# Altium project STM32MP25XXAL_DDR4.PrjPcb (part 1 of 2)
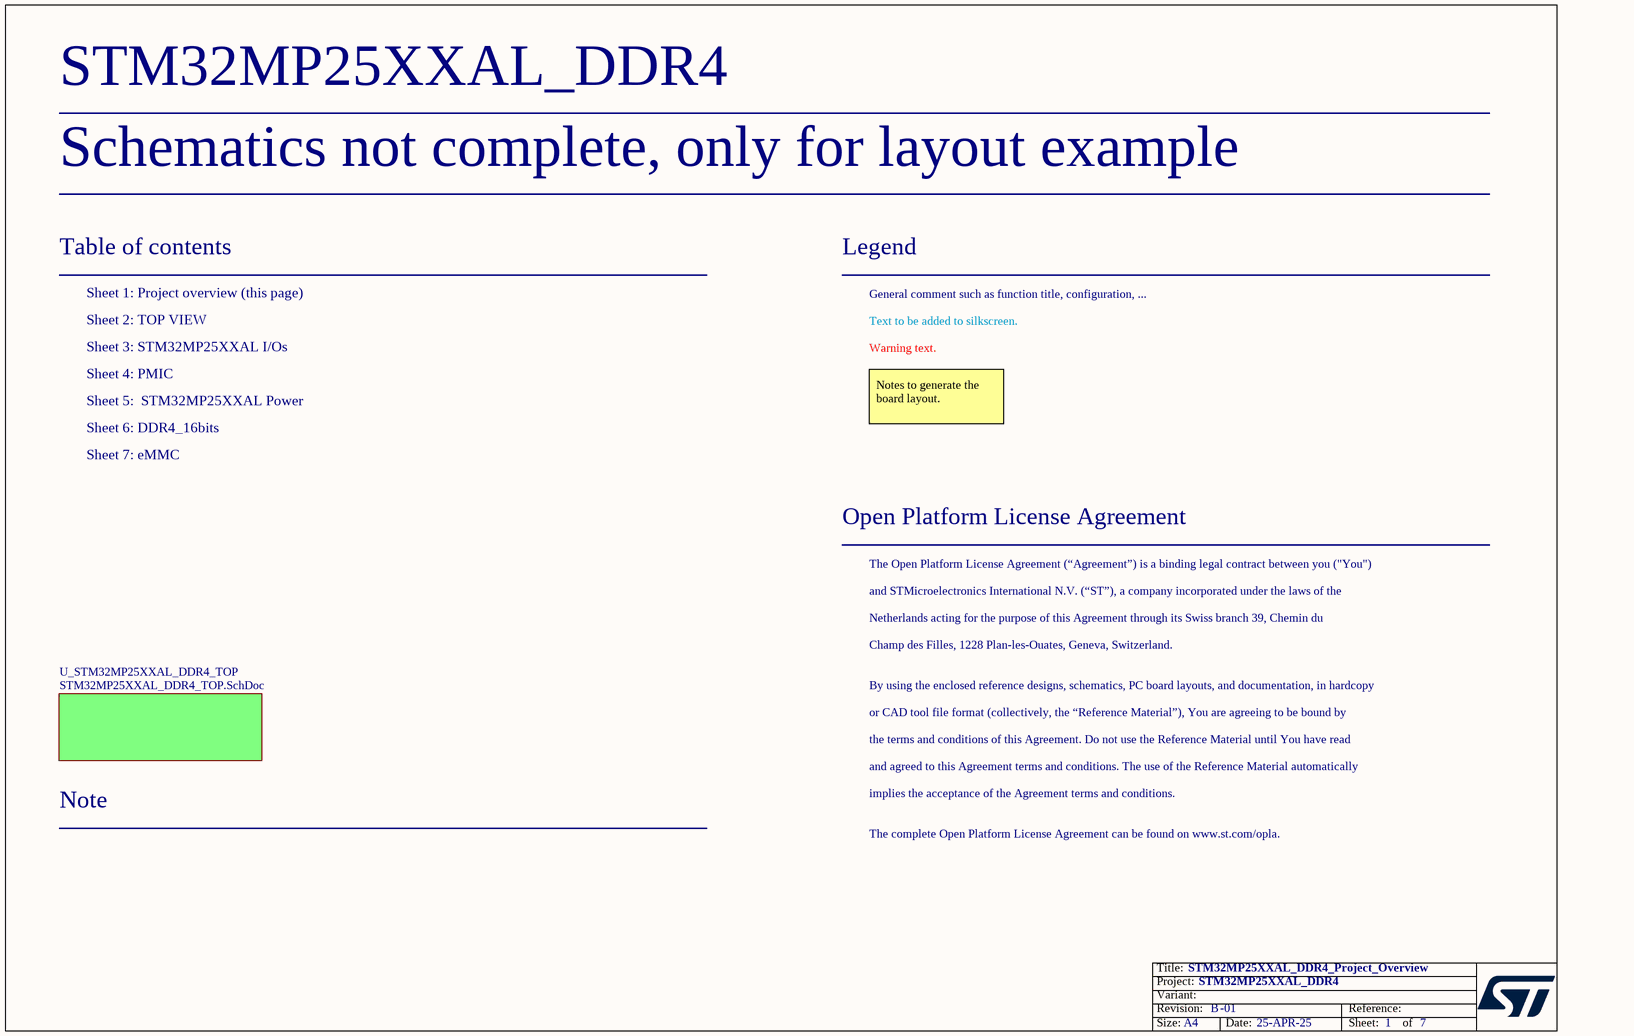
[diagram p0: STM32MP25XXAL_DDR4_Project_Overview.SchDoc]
Board_Assembly_Revision: 01; Board_Document_Date: 25-APR-25; Board_Name: STM32MP25XXAL_DDR4; Board_PCB_Revision: B
7 sheets, 220 parts. Net scope: flat (ports and power ports of the same name join across sheets).
Board file: STM32MP25XXAL_DDR4.PcbDoc
Sheets:
  STM32MP25XXAL_DDR4_Project_Overview.SchDoc
    U_STM32MP25XXAL_DDR4_TOP = STM32MP25XXAL_DDR4_TOP.SchDoc
      U_STM32MP25XXAL I_Os = STM32MP25XXAL I_Os.SchDoc
      U_PMIC = PMIC.SchDoc
      U_STM32MP25XXAL Power = STM32MP25XXAL Power.SchDoc
      U_eMMC = eMMC.SchDoc
      U_DDR4_16bits = DDR4_16bits.SchDoc

## Sheet STM32MP25XXAL_DDR4_Project_Overview.SchDoc: STM32MP25XXAL_DDR4_Project_Overview
size A4; Date: Not used; ApprovedBy: Not used; CheckedBy: Not used; Author: Not used; CompanyName: STMicroelectronics; DrawnBy: Not used; Engineer: Not used; Organization: Not used; Address1: Not used; Address2: Not used; Address3: Not used; Address4: Not used; DocumentNumber: 1; Revision: Not used; SheetNumber: 1; SheetTotal: 7

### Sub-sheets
U_STM32MP25XXAL_DDR4_TOP = STM32MP25XXAL_DDR4_TOP.SchDoc: no entries

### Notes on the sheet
- Schematics not complete, only for layout example
- Table of contents
- Sheet 1: Project overview (this page)
- Legend
- General comment such as function title, configuration, ...
- Sheet 2: TOP VIEW
- Sheet 3: STM32MP25XXAL I/Os
- Sheet 4: PMIC
- Text to be added to silkscreen.
- Warning text.
- Sheet 5:  STM32MP25XXAL Power
- Sheet 6: DDR4_16bits
- Notes to generate the board layout.
- Sheet 7: eMMC
- Open Platform License Agreement
- The Open Platform License Agreement (“Agreement”) is a binding legal contract between you ("You")
- and STMicroelectronics International N.V. (“ST”), a company incorporated under the laws of the
- Netherlands acting for the purpose of this Agreement through its Swiss branch 39, Chemin du
- Champ des Filles, 1228 Plan-les-Ouates, Geneva, Switzerland.
- By using the enclosed reference designs, schematics, PC board layouts, and documentation, in hardcopy
- or CAD tool file format (collectively, the “Reference Material”), You are agreeing to be bound by
- the terms and conditions of this Agreement. Do not use the Reference Material until You have read
- and agreed to this Agreement terms and conditions. The use of the Reference Material automatically
- Note
- implies the acceptance of the Agreement terms and conditions.
- The complete Open Platform License Agreement can be found on www.st.com/opla.

## Sheet STM32MP25XXAL_DDR4_TOP.SchDoc: TOP
size A4; Date: Not used; ApprovedBy: Not used; CheckedBy: Not used; Author: Not used; CompanyName: STMicroelectronics; DrawnBy: Not used; Engineer: Not used; Organization: Not used; Address1: Not used; Address2: Not used; Address3: Not used; Address4: Not used; DocumentNumber: 2; Revision: Not used; SheetNumber: 2; SheetTotal: 7
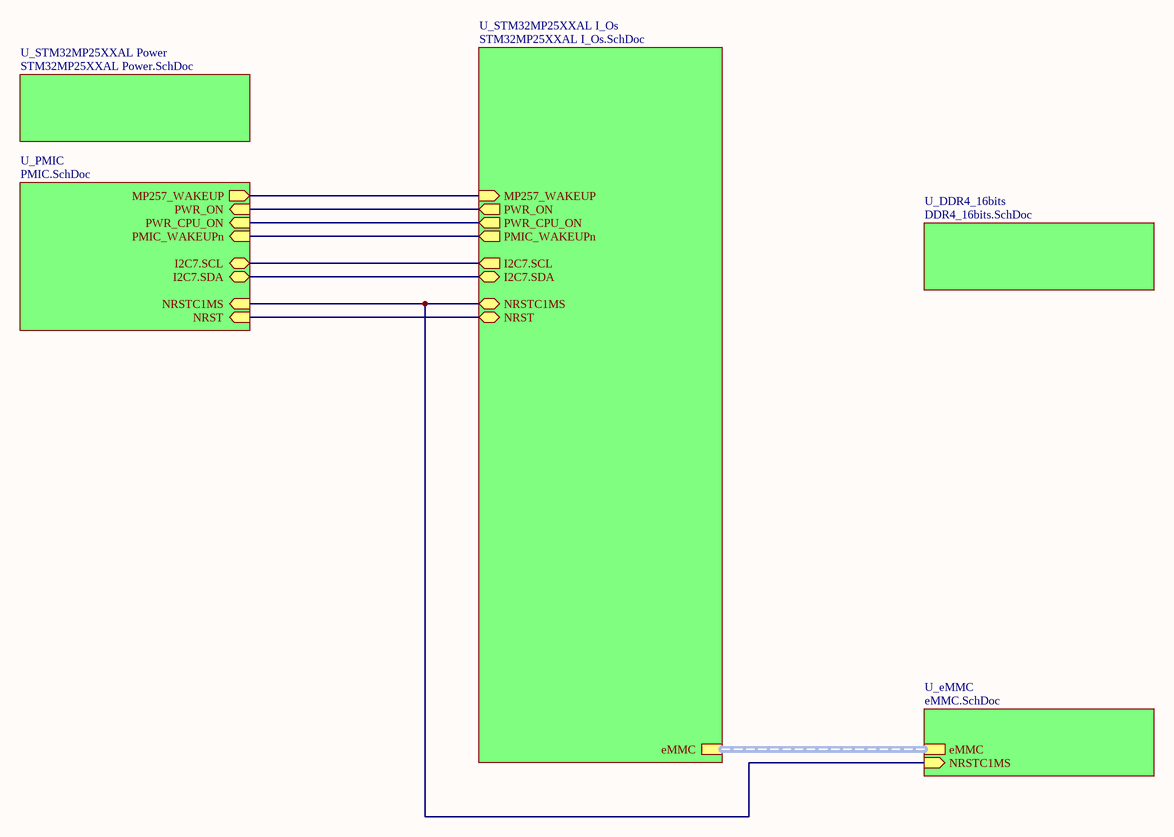
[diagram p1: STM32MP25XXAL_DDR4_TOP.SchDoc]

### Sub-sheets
U_DDR4_16bits = DDR4_16bits.SchDoc: no entries
U_eMMC = eMMC.SchDoc: eMMC (harness eMMC), NRSTC1MS (in)
U_PMIC = PMIC.SchDoc: PMIC_WAKEUPn (in), NRST (in), I2C7.SCL (bidir), PWR_ON (in), PWR_CPU_ON (in), NRSTC1MS (in), I2C7.SDA (bidir), MP257_WAKEUP (out)
U_STM32MP25XXAL I_Os = STM32MP25XXAL I_Os.SchDoc: NRST (bidir), PWR_ON (out), NRSTC1MS (bidir), I2C7.SDA (bidir), I2C7.SCL (out), PWR_CPU_ON (out), MP257_WAKEUP (in), PMIC_WAKEUPn (out), eMMC (harness eMMC)
U_STM32MP25XXAL Power = STM32MP25XXAL Power.SchDoc: no entries

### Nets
(unnamed): sheet U_STM32MP25XXAL I_Os/NRST, sheet U_PMIC/NRST
(unnamed): sheet U_STM32MP25XXAL I_Os/PWR_ON, sheet U_PMIC/PWR_ON  [a separate net that carries the same name]
(unnamed): sheet U_STM32MP25XXAL I_Os/NRSTC1MS, sheet U_PMIC/NRSTC1MS, sheet U_eMMC/NRSTC1MS  [a separate net that carries the same name]
(unnamed): sheet U_STM32MP25XXAL I_Os/I2C7.SDA, sheet U_PMIC/I2C7.SDA  [a separate net that carries the same name]
(unnamed): sheet U_STM32MP25XXAL I_Os/I2C7.SCL, sheet U_PMIC/I2C7.SCL  [a separate net that carries the same name]
(unnamed): sheet U_STM32MP25XXAL I_Os/PWR_CPU_ON, sheet U_PMIC/PWR_CPU_ON  [a separate net that carries the same name]
(unnamed): sheet U_STM32MP25XXAL I_Os/MP257_WAKEUP, sheet U_PMIC/MP257_WAKEUP  [a separate net that carries the same name]
(unnamed): sheet U_STM32MP25XXAL I_Os/PMIC_WAKEUPn, sheet U_PMIC/PMIC_WAKEUPn  [a separate net that carries the same name]

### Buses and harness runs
harness sheet U_eMMC/eMMC = sheet U_STM32MP25XXAL I_Os/eMMC

## Sheet STM32MP25XXAL I_Os.SchDoc: STM32MP25XXAL  I/Os
size A3; Date: Not used; ApprovedBy: Not used; CheckedBy: Not used; Author: Not used; CompanyName: STMicroelectronics; DrawnBy: Not used; Engineer: Not used; Organization: Not used; Address1: Not used; Address2: Not used; Address3: Not used; Address4: Not used; DocumentNumber: 3; Revision: Not used; SheetNumber: 3; SheetTotal: 7
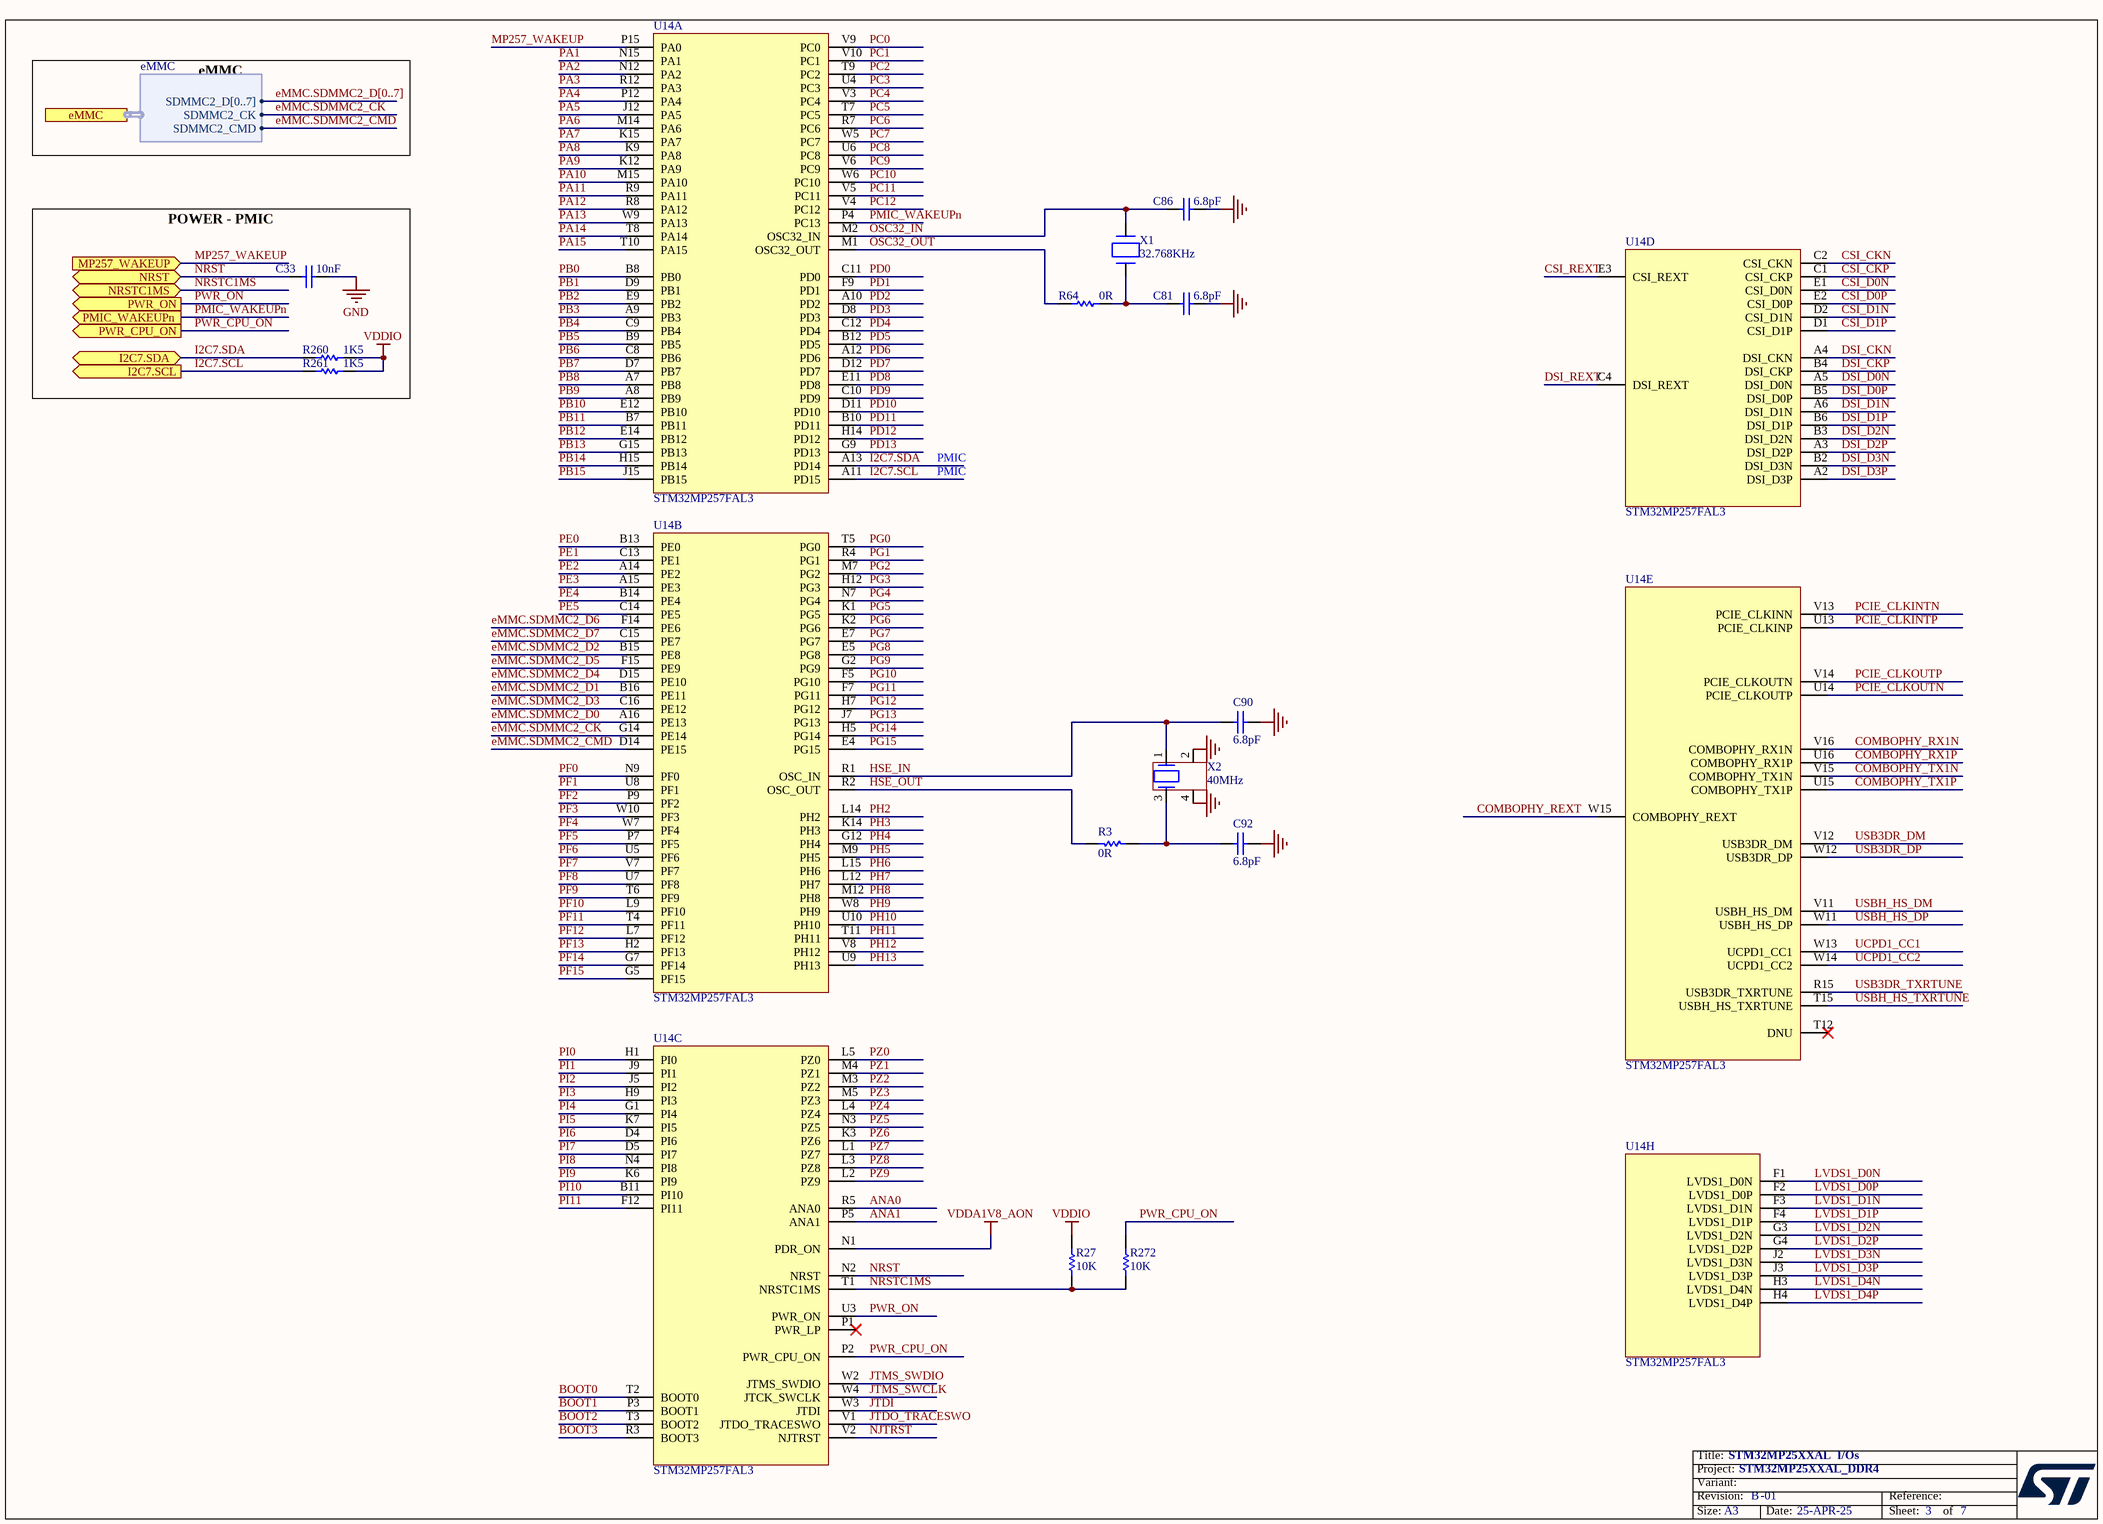
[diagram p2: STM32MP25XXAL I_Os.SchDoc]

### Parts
C33  value 10nF  [C0402]  (hidden comment: Capacitor)
C81  value 6.8pF  [C0402]  (hidden comment: Capacitor)
C86  value 6.8pF  [C0402]  (hidden comment: Capacitor)
C90  value 6.8pF  [C0402]  (hidden comment: Capacitor)
C92  value 6.8pF  [C0402]  (hidden comment: Capacitor)
R3  value 0R  [R0402]
R27  value 10K  [R0402]  (hidden comment: Resistor)
R64  value 0R  [R0402]
R260  value 1K5  [R0402]  (hidden comment: Resistor)
R261  value 1K5  [R0402]  (hidden comment: Resistor)
R272  value 10K  [R0402]  (hidden comment: Resistor)
U14  STM32MP257FAL3  [ICC_VFBGA361_10X10_P050]  (parts A,B,C,D,E,H of 8)
X1  value 32.768KHz  [CRY_NX2012SA_2P]  (hidden comment: XTAL_2_PINS)
X2  value 40MHz  [CRY_NX1612SA_4P]  (hidden comment: XTAL_4_PINS)

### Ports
eMMC (harness eMMC), I2C7.SCL (out), I2C7.SDA (bidir), MP257_WAKEUP (in), NRST (bidir), NRSTC1MS (bidir), PMIC_WAKEUPn (out), PWR_CPU_ON (out), PWR_ON (out)

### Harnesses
eMMC: SDMMC2_CK, SDMMC2_CMD, SDMMC2_D[0..7]

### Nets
GND: C33.1 C81.2 C86.2 C90.1 C92.2 X2.2 X2.4
VDDA1V8_AON: U14.N1(PDR_ON)
VDDIO: R27.2 R260.2 R261.2
ANA0: U14.R5(ANA0)
ANA1: U14.P5(ANA1)
BOOT0: U14.T2(BOOT0)
BOOT1: U14.P3(BOOT1)
BOOT2: U14.T3(BOOT2)
BOOT3: U14.R3(BOOT3)
COMBOPHY_REXT: U14.W15(COMBOPHY_REXT)
COMBOPHY_RX1N: U14.V16(COMBOPHY_RX1N)
COMBOPHY_RX1P: U14.U16(COMBOPHY_RX1P)
COMBOPHY_TX1N: U14.V15(COMBOPHY_TX1N)
COMBOPHY_TX1P: U14.U15(COMBOPHY_TX1P)
CSI_CKN: U14.C2(CSI_CKN)
CSI_CKP: U14.C1(CSI_CKP)
CSI_D0N: U14.E1(CSI_D0N)
CSI_D0P: U14.E2(CSI_D0P)
CSI_D1N: U14.D2(CSI_D1N)
CSI_D1P: U14.D1(CSI_D1P)
CSI_REXT: U14.E3(CSI_REXT)
DSI_CKN: U14.A4(DSI_CKN)
DSI_CKP: U14.B4(DSI_CKP)
DSI_D0N: U14.A5(DSI_D0N)
DSI_D0P: U14.B5(DSI_D0P)
DSI_D1N: U14.A6(DSI_D1N)
DSI_D1P: U14.B6(DSI_D1P)
DSI_D2N: U14.B3(DSI_D2N)
DSI_D2P: U14.A3(DSI_D2P)
DSI_D3N: U14.B2(DSI_D3N)
DSI_D3P: U14.A2(DSI_D3P)
DSI_REXT: U14.C4(DSI_REXT)
eMMC.SDMMC2_CK: U14.G14(PE14) ; port eMMC.SDMMC2_CK
eMMC.SDMMC2_CMD: U14.D14(PE15) ; port eMMC.SDMMC2_CMD
eMMC.SDMMC2_D0: U14.A16(PE13)
eMMC.SDMMC2_D1: U14.B16(PE11)
eMMC.SDMMC2_D2: U14.B15(PE8)
eMMC.SDMMC2_D3: U14.C16(PE12)
eMMC.SDMMC2_D4: U14.D15(PE10)
eMMC.SDMMC2_D5: U14.F15(PE9)
eMMC.SDMMC2_D6: U14.F14(PE6)
eMMC.SDMMC2_D7: U14.C15(PE7)
HSE_IN: C90.2 U14.R1(OSC_IN) X2.1
HSE_OUT: R3.2 U14.R2(OSC_OUT)
I2C7.SCL: R261.1 U14.A11(PD15) ; port I2C7.SCL
I2C7.SDA: R260.1 U14.A13(PD14) ; port I2C7.SDA
JTDI: U14.W3(JTDI)
JTDO_TRACESWO: U14.V1(JTDO_TRACESWO)
JTMS_SWCLK: U14.W4(JTCK_SWCLK)
JTMS_SWDIO: U14.W2(JTMS_SWDIO)
LVDS1_D0N: U14.F1(LVDS1_D0N)
LVDS1_D0P: U14.F2(LVDS1_D0P)
LVDS1_D1N: U14.F3(LVDS1_D1N)
LVDS1_D1P: U14.F4(LVDS1_D1P)
LVDS1_D2N: U14.G3(LVDS1_D2N)
LVDS1_D2P: U14.G4(LVDS1_D2P)
LVDS1_D3N: U14.J2(LVDS1_D3N)
LVDS1_D3P: U14.J3(LVDS1_D3P)
LVDS1_D4N: U14.H3(LVDS1_D4N)
LVDS1_D4P: U14.H4(LVDS1_D4P)
MP257_WAKEUP: U14.P15(PA0) ; port MP257_WAKEUP
NJTRST: U14.V2(NJTRST)
NRST: C33.2 U14.N2(NRST) ; port NRST
NRSTC1MS: R27.1 R272.1 U14.T1(NRSTC1MS) ; port NRSTC1MS
OSC32_IN: C86.1 U14.M2(OSC32_IN) X1.2(X2)
OSC32_OUT: R64.1 U14.M1(OSC32_OUT)
PA1: U14.N15(PA1)
PA2: U14.N12(PA2)
PA3: U14.R12(PA3)
PA4: U14.P12(PA4)
PA5: U14.J12(PA5)
PA6: U14.M14(PA6)
PA7: U14.K15(PA7)
PA8: U14.K9(PA8)
PA9: U14.K12(PA9)
PA10: U14.M15(PA10)
PA11: U14.R9(PA11)
PA12: U14.R8(PA12)
PA13: U14.W9(PA13)
PA14: U14.T8(PA14)
PA15: U14.T10(PA15)
PB0: U14.B8(PB0)
PB1: U14.D9(PB1)
PB2: U14.E9(PB2)
PB3: U14.A9(PB3)
PB4: U14.C9(PB4)
PB5: U14.B9(PB5)
PB6: U14.C8(PB6)
PB7: U14.D7(PB7)
PB8: U14.A7(PB8)
PB9: U14.A8(PB9)
PB10: U14.E12(PB10)
PB11: U14.B7(PB11)
PB12: U14.E14(PB12)
PB13: U14.G15(PB13)
PB14: U14.H15(PB14)
PB15: U14.J15(PB15)
PC0: U14.V9(PC0)
PC1: U14.V10(PC1)
PC2: U14.T9(PC2)
PC3: U14.U4(PC3)
PC4: U14.V3(PC4)
PC5: U14.T7(PC5)
PC6: U14.R7(PC6)
PC7: U14.W5(PC7)
PC8: U14.U6(PC8)
PC9: U14.V6(PC9)
PC10: U14.W6(PC10)
PC11: U14.V5(PC11)
PC12: U14.V4(PC12)
PCIE_CLKINTN: U14.V13(PCIE_CLKINN)
PCIE_CLKINTP: U14.U13(PCIE_CLKINP)
PCIE_CLKOUTN: U14.U14(PCIE_CLKOUTP)
PCIE_CLKOUTP: U14.V14(PCIE_CLKOUTN)
PD0: U14.C11(PD0)
PD1: U14.F9(PD1)
PD2: U14.A10(PD2)
PD3: U14.D8(PD3)
PD4: U14.C12(PD4)
PD5: U14.B12(PD5)
PD6: U14.A12(PD6)
PD7: U14.D12(PD7)
PD8: U14.E11(PD8)
PD9: U14.C10(PD9)
PD10: U14.D11(PD10)
PD11: U14.B10(PD11)
PD12: U14.H14(PD12)
PD13: U14.G9(PD13)
PE0: U14.B13(PE0)
PE1: U14.C13(PE1)
PE2: U14.A14(PE2)
PE3: U14.A15(PE3)
PE4: U14.B14(PE4)
PE5: U14.C14(PE5)
PF0: U14.N9(PF0)
PF1: U14.U8(PF1)
PF2: U14.P9(PF2)
PF3: U14.W10(PF3)
PF4: U14.W7(PF4)
PF5: U14.P7(PF5)
PF6: U14.U5(PF6)
PF7: U14.V7(PF7)
PF8: U14.U7(PF8)
PF9: U14.T6(PF9)
PF10: U14.L9(PF10)
PF11: U14.T4(PF11)
PF12: U14.L7(PF12)
PF13: U14.H2(PF13)
PF14: U14.G7(PF14)
PF15: U14.G5(PF15)
PG0: U14.T5(PG0)
PG1: U14.R4(PG1)
PG2: U14.M7(PG2)
PG3: U14.H12(PG3)
PG4: U14.N7(PG4)
PG5: U14.K1(PG5)
PG6: U14.K2(PG6)
PG7: U14.E7(PG7)
PG8: U14.E5(PG8)
PG9: U14.G2(PG9)
PG10: U14.F5(PG10)
PG11: U14.F7(PG11)
PG12: U14.H7(PG12)
PG13: U14.J7(PG13)
PG14: U14.H5(PG14)
PG15: U14.E4(PG15)
PH2: U14.L14(PH2)
PH3: U14.K14(PH3)
PH4: U14.G12(PH4)
PH5: U14.M9(PH5)
PH6: U14.L15(PH6)
PH7: U14.L12(PH7)
PH8: U14.M12(PH8)
PH9: U14.W8(PH9)
PH10: U14.U10(PH10)
PH11: U14.T11(PH11)
PH12: U14.V8(PH12)
PH13: U14.U9(PH13)
PI0: U14.H1(PI0)
PI1: U14.J9(PI1)
PI2: U14.J5(PI2)
PI3: U14.H9(PI3)
PI4: U14.G1(PI4)
PI5: U14.K7(PI5)
PI6: U14.D4(PI6)
PI7: U14.D5(PI7)
PI8: U14.N4(PI8)
PI9: U14.K6(PI9)
PI10: U14.B11(PI10)
PI11: U14.F12(PI11)
PMIC_WAKEUPn: U14.P4(PC13) ; port PMIC_WAKEUPn
PWR_CPU_ON: R272.2 U14.P2(PWR_CPU_ON) ; port PWR_CPU_ON
PWR_ON: U14.U3(PWR_ON) ; port PWR_ON
PZ0: U14.L5(PZ0)
PZ1: U14.M4(PZ1)
PZ2: U14.M3(PZ2)
PZ3: U14.M5(PZ3)
PZ4: U14.L4(PZ4)
PZ5: U14.N3(PZ5)
PZ6: U14.K3(PZ6)
PZ7: U14.L1(PZ7)
PZ8: U14.L3(PZ8)
PZ9: U14.L2(PZ9)
UCPD1_CC1: U14.W13(UCPD1_CC1)
UCPD1_CC2: U14.W14(UCPD1_CC2)
USB3DR_DM: U14.V12(USB3DR_DM)
USB3DR_DP: U14.W12(USB3DR_DP)
USB3DR_TXRTUNE: U14.R15(USB3DR_TXRTUNE)
USBH_HS_DM: U14.V11(USBH_HS_DM)
USBH_HS_DP: U14.W11(USBH_HS_DP)
USBH_HS_TXRTUNE: U14.T15(USBH_HS_TXRTUNE)
NetC81_1: C81.1 R64.2 X1.1(X1)
NetC92_1: C92.1 R3.1 X2.3

Not connected (* = marked no-connect by the designer): U14 P1(PWR_LP)* T12(DNU)*

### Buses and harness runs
bus eMMC.SDMMC2_D[0..7]

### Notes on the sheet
- eMMC
- POWER - PMIC
- PMIC

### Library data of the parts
C33 = MCD-00011: Capacitor, MLCC, 10nF, 16V, X7R, 10%, 0402, T=0.5mm; Manufacturer_Part_Number: CC0402KRX7R7BB103; Manufacturer: YAGEO; Provided_By: SUBCO; Initial_Board_Reference: MB1274
C81 C86 = MCD-00674: Capacitor, MLCC, 6.8pF, 50V, NPO, +-0.25pF, 0402, T=0.5mm; Manufacturer_Part_Number: CC0402CRNPO9BN6R8; Manufacturer: YAGEO; Part_Preference: Recommended; Provided_By: SUBCO; Initial_Board_Reference: MB1319; Path: ws/MCD_ApplicationBoards/Lists/MCDPARTSdatabase; Item Type: Item; Component_Country_Of_Origin: China; ID: 3068; ShowFields: YES
C90 C92 = MCD-00674: Capacitor, MLCC, 6.8pF, 50V, NPO, +-0.25pF, 0402, T=0.5mm; Manufacturer_Part_Number: CC0402CRNPO9BN6R8; Manufacturer: YAGEO; Part_Preference: Recommended; Provided_By: SUBCO; Initial_Board_Reference: MB1319; Component_Country_Of_Origin: China; ID: 3068; ShowFields: YES
R3 R64 = MCD-00052: Resistor,0R,0402,5%,1/16W; Manufacturer_Part_Number: RC0402JR-070RL; Manufacturer: YAGEO; Part_Preference: Recommended; Provided_By: SUBCO; Initial_Board_Reference: mb1274; Order_Code_RS: 618-5804; Component_Country_Of_Origin: China; ID: 2540; ShowFields: YES
R27 R272 = MCD-00053: Resistor,10K,0402,1%,1/16W; BMS_Part_Number: 9131590; Part_Preference: Recommended; Manufacturer: YAGEO; Manufacturer_Part_Number: RC0402FR-0710KL; Component_Country_Of_Origin: China; ID: 2539; ShowFields: YES
R260 R261 = MCD-00068: Resistor,1K5,0402,1%,1/16W; Part_Preference: Recommended; Manufacturer: YAGEO; Manufacturer_Part_Number: RC0402FR-071K5L; Component_Country_Of_Origin: China; ID: 2524; ShowFields: YES
U14 = MCD-03768: MPU, dual core ARM cortex-A35 64-bit + M33 32-bit, 808KB SRAM, With Crypto; Part_Type: IC; Part_Preference: Recommended; Manufacturer: STMICROELECTRONICS; Component_Country_Of_Origin: Unknown; ShowFields: YES; ID: 5884
X1 = MCD-01479: Crystal, 32.768kHz, 6pF, +/-20ppm, 80K, 2.05x1.2mm; BMS_Part_Number: 9157049; Part_Type: Crystal_Osc; Part_Preference: Recommended; Manufacturer: NDK; Manufacturer_Part_Number: NX2012SA-32.768KHZ-EXS00A-MU00527; Component_Country_Of_Origin: Unknown; ShowFields: YES; ID: 3579
X2 = MCD-02344: Crystal, 40MHz, 6pF, +/-20ppm, 80R, 1.6x1.2mm; Part_Type: Crystal_Osc; Part_Preference: Recommended; Manufacturer: NDK; Manufacturer_Part_Number: NX1612SA-40MHZ-EXS00A-CS13836; Component_Country_Of_Origin: Unknown; ShowFields: YES; ID: 4450

## Sheet PMIC.SchDoc: PMIC
size A3; Date: Not used; ApprovedBy: Not used; CheckedBy: Not used; Author: Not used; CompanyName: STMicroelectronics; DrawnBy: Not used; Engineer: Not used; Organization: Not used; Address1: Not used; Address2: Not used; Address3: Not used; Address4: Not used; DocumentNumber: 4; Revision: Not used; SheetNumber: 4; SheetTotal: 7
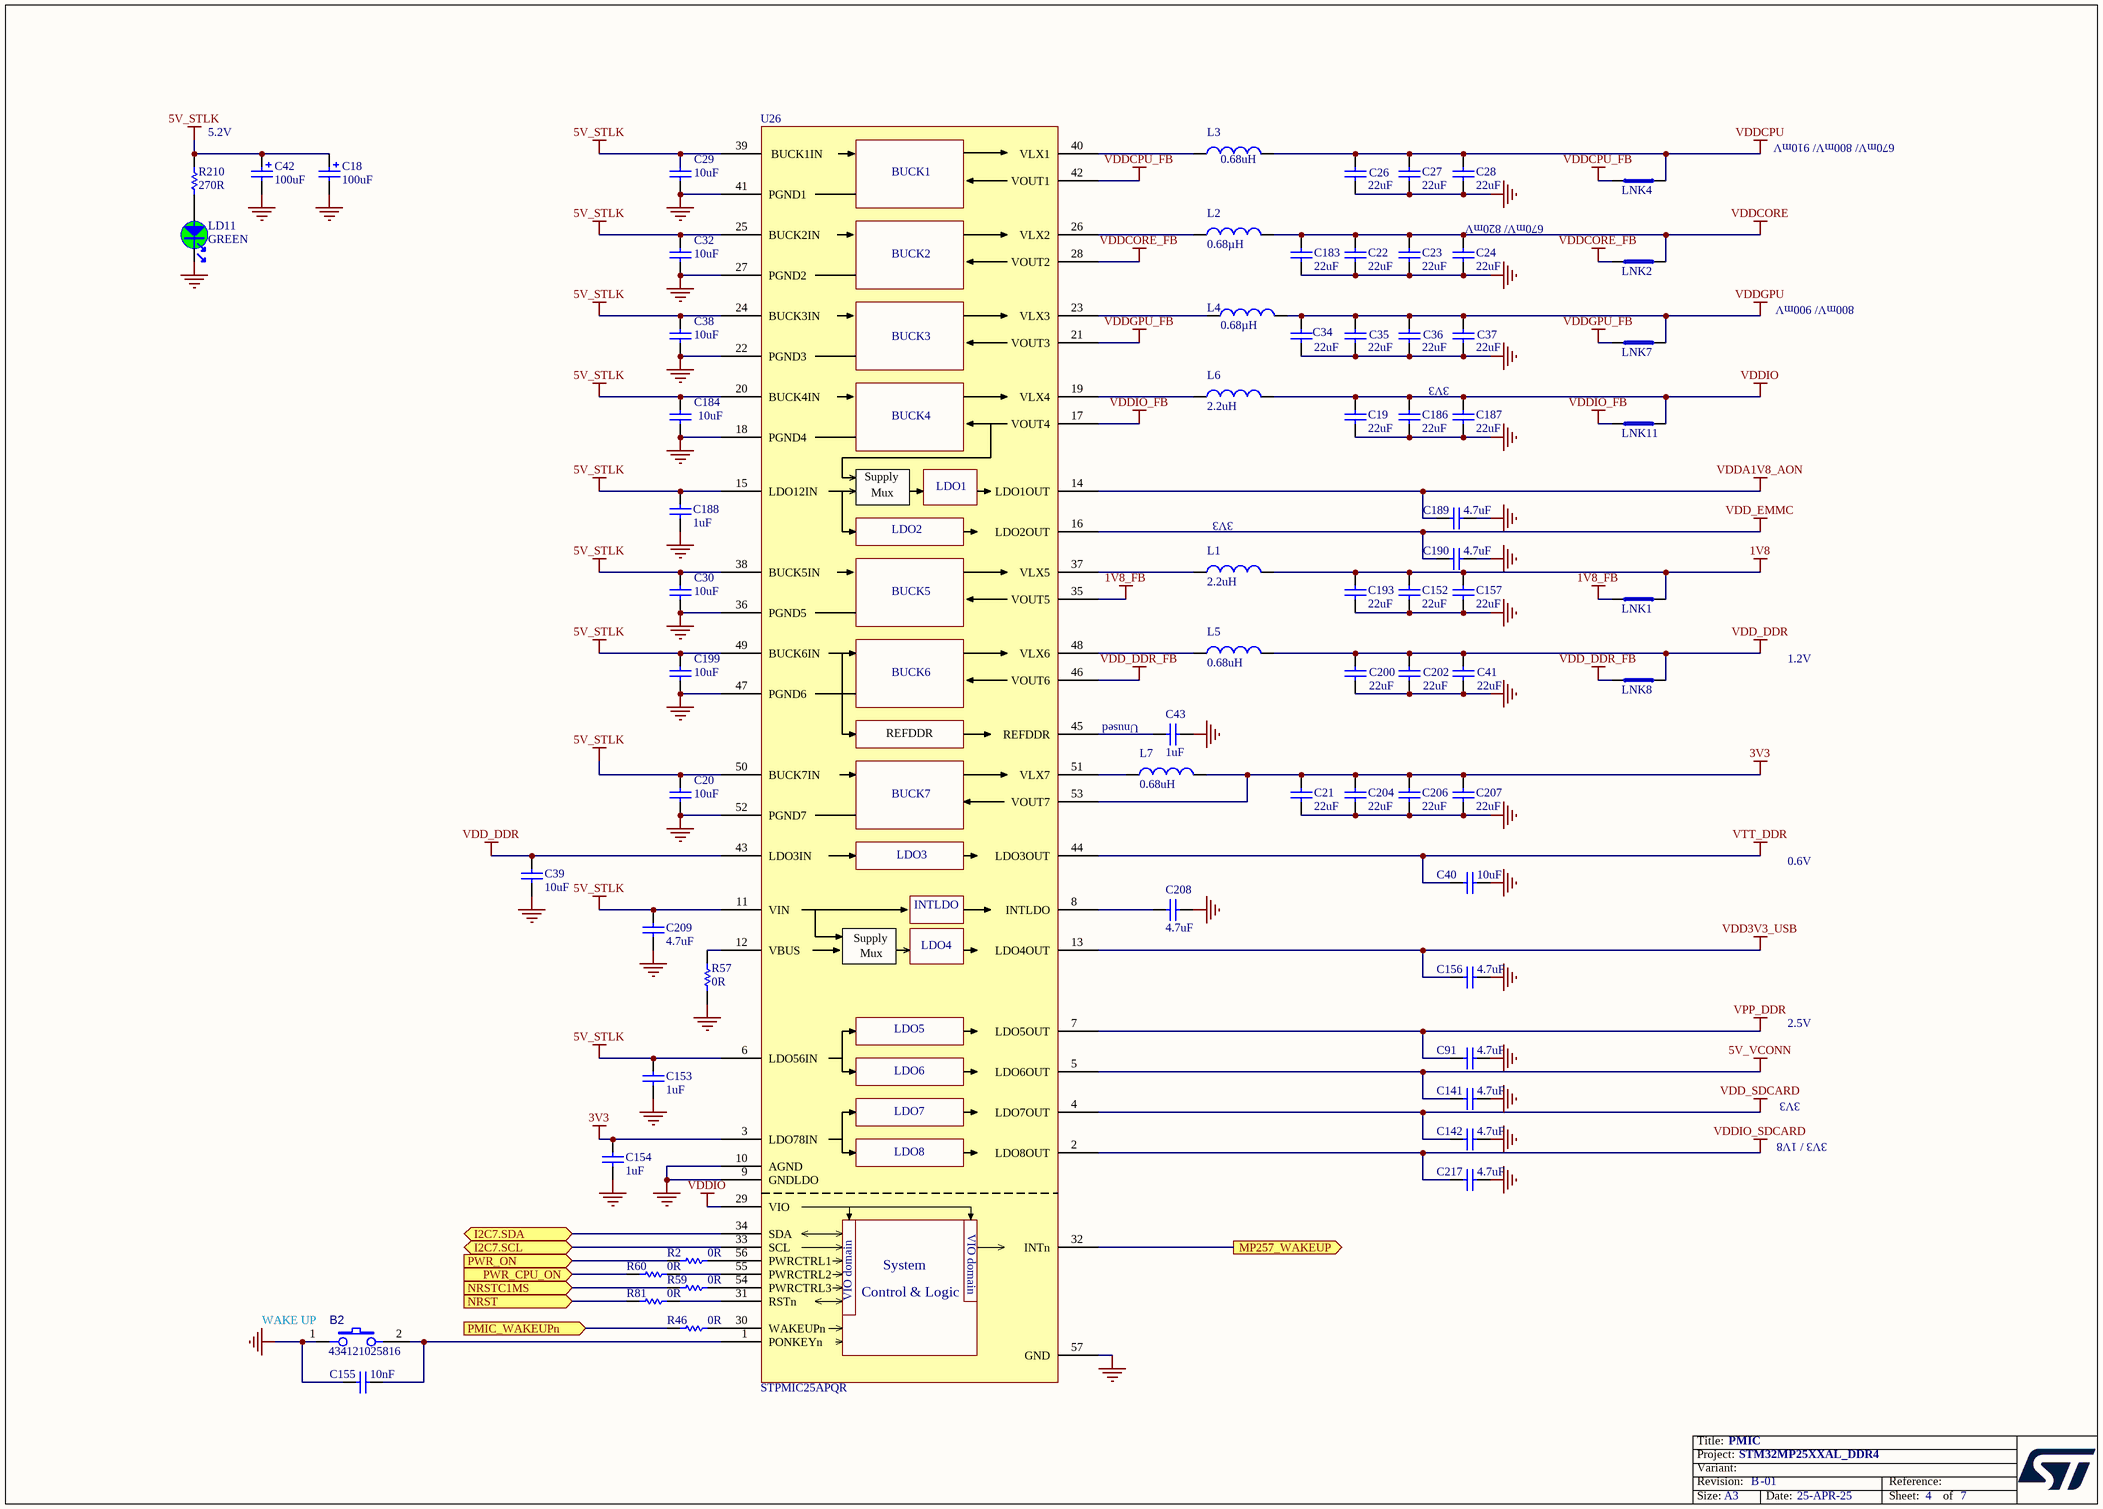
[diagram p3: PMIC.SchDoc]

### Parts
B2  value 434121025816  [SWI_WE_434121025816]  (hidden comment: SW_PUSH_SMD_2P)
C18  value 100uF  [CPOL_TCJ-B_1210_H210]  (hidden comment: Cap_POL_TANA)
C19  value 22uF  [C0805]  (hidden comment: Capacitor)
C20  value 10uF  [C0603]  (hidden comment: Capacitor)
C21  value 22uF  [C0805]  (hidden comment: Capacitor)
C22  value 22uF  [C0603]  (hidden comment: Capacitor)
C23  value 22uF  [C0603]  (hidden comment: Capacitor)
C24  value 22uF  [C0603]  (hidden comment: Capacitor)
C26  value 22uF  [C0603]  (hidden comment: Capacitor)
C27  value 22uF  [C0603]  (hidden comment: Capacitor)
C28  value 22uF  [C0603]  (hidden comment: Capacitor)
C29  value 10uF  [C0603]  (hidden comment: Capacitor)
C30  value 10uF  [C0603]  (hidden comment: Capacitor)
C32  value 10uF  [C0603]  (hidden comment: Capacitor)
C34  value 22uF  [C0603]  (hidden comment: Capacitor)
C35  value 22uF  [C0603]  (hidden comment: Capacitor)
C36  value 22uF  [C0603]  (hidden comment: Capacitor)
C37  value 22uF  [C0603]  (hidden comment: Capacitor)
C38  value 10uF  [C0603]  (hidden comment: Capacitor)
C39  value 10uF  [C0402]  (hidden comment: Capacitor)
C40  value 10uF  [C0402]  (hidden comment: Capacitor)
C41  value 22uF  [C0603]  (hidden comment: Capacitor)
C42  value 100uF  [CPOL_TCJ-B_1210_H210]  (hidden comment: Cap_POL_TANA)
C43  value 1uF  [C0402]  (hidden comment: Capacitor)
C91  value 4.7uF  [C0402]  (hidden comment: Capacitor)
C141  value 4.7uF  [C0402]  (hidden comment: Capacitor)
C142  value 4.7uF  [C0402]  (hidden comment: Capacitor)
C152  value 22uF  [C0805]  (hidden comment: Capacitor)
C153  value 1uF  [C0402]  (hidden comment: Capacitor)
C154  value 1uF  [C0402]  (hidden comment: Capacitor)
C155  value 10nF  [C0402]  (hidden comment: Capacitor)
C156  value 4.7uF  [C0402]  (hidden comment: Capacitor)
C157  value 22uF  [C0805]  (hidden comment: Capacitor)
C183  value 22uF  [C0603]  (hidden comment: Capacitor)
C184  value 10uF  [C0603]  (hidden comment: Capacitor)
C186  value 22uF  [C0805]  (hidden comment: Capacitor)
C187  value 22uF  [C0805]  (hidden comment: Capacitor)
C188  value 1uF  [C0402]  (hidden comment: Capacitor)
C189  value 4.7uF  [C0402]  (hidden comment: Capacitor)
C190  value 4.7uF  [C0402]  (hidden comment: Capacitor)
C193  value 22uF  [C0805]  (hidden comment: Capacitor)
C199  value 10uF  [C0603]  (hidden comment: Capacitor)
C200  value 22uF  [C0603]  (hidden comment: Capacitor)
C202  value 22uF  [C0603]  (hidden comment: Capacitor)
C204  value 22uF  [C0805]  (hidden comment: Capacitor)
C206  value 22uF  [C0805]  (hidden comment: Capacitor)
C207  value 22uF  [C0805]  (hidden comment: Capacitor)
C208  value 4.7uF  [C0402]  (hidden comment: Capacitor)
C209  value 4.7uF  [C0402]  (hidden comment: Capacitor)
C217  value 4.7uF  [C0402]  (hidden comment: Capacitor)
L1  value 2.2uH  [IND_2016_MURATA_LQM2MPN2R2NG0]  (hidden comment: Inductor)
L2  value 0.68µH  [IND_2520_TOKO_DFE252012P]  (hidden comment: Inductor)
L3  value 0.68uH  [IND_2016_MURATA_LQM2MPN2R2NG0]  (hidden comment: Inductor)
L4  value 0.68µH  [IND_2520_TOKO_DFE252012P]  (hidden comment: Inductor)
L5  value 0.68uH  [IND_2016_MURATA_LQM2MPN2R2NG0]  (hidden comment: Inductor)
L6  value 2.2uH  [IND_2016_MURATA_LQM2MPN2R2NG0]  (hidden comment: Inductor)
L7  value 0.68uH  [IND_2016_MURATA_LQM2MPN2R2NG0]  (hidden comment: Inductor)
LD11  value GREEN  [LED_0603_OSRAM_LG-Q396-PS-35_GREEN_1A2K_H0P4]  (hidden comment: LED_green)
LNK1  link_200  [LINK200]  (value not drawn)  (no BOM)
LNK2  link_200  [LINK200]  (value not drawn)  (no BOM)
LNK4  link_200  [LINK200]  (value not drawn)  (no BOM)
LNK7  link_200  [LINK200]  (value not drawn)  (no BOM)
LNK8  link_200  [LINK200]  (value not drawn)  (no BOM)
LNK11  link_200  [LINK200]  (value not drawn)  (no BOM)
R2  value 0R  [R0402]
R46  value 0R  [R0402]
R57  value 0R  [R0402]
R59  value 0R  [R0402]
R60  value 0R  [R0402]
R81  value 0R  [R0402]
R210  value 270R  [R0402]  (hidden comment: Resistor)
U26  STPMIC25APQR  [ICC_QFN56-EPAD_6P5X6P5_P040]

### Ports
I2C7.SCL (bidir), I2C7.SDA (bidir), MP257_WAKEUP (out), NRST (in), NRSTC1MS (in), PMIC_WAKEUPn (in), PWR_CPU_ON (in), PWR_ON (in)

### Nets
1V8: C152.2 C157.2 C193.2 L1.2 LNK1.2
1V8_FB: LNK1.1 U26.35(VOUT5)
3V3: C21.2 C154.2 C204.2 C206.2 C207.2 L7.2 U26.3(LDO78IN) U26.53(VOUT7)
5V_STLK: C18.1 C20.2 C29.2 C30.2 C32.2 C38.2 C42.1 C153.2 C184.2 C188.2 C199.2 C209.2 R210.1 U26.6(LDO56IN) U26.11(VIN) U26.15(LDO12IN) U26.20(BUCK4IN) U26.24(BUCK3IN) U26.25(BUCK2IN) U26.38(BUCK5IN) U26.39(BUCK1IN) U26.49(BUCK6IN) U26.50(BUCK7IN)
5V_VCONN: C141.1 U26.5(LDO6OUT)
GND: B2.1 C18.2 C19.1 C20.1 C21.1 C22.1 C23.1 C24.1 C26.1 C27.1 C28.1 C29.1 C30.1 C32.1 C34.1 C35.1 C36.1 C37.1 C38.1 C39.1 C40.1 C41.1 C42.2 C43.1 C91.2 C141.2 C142.2 C152.1 C153.1 C154.1 C155.1 C156.1 C157.1 C183.1 C184.1 C186.1 C187.1 C188.1 C189.1 C190.2 C193.1 C199.1 C200.1 C202.1 C204.1 C206.1 C207.1 C208.2 C209.1 C217.2 LD11.2 R57.1 U26.9(GNDLDO) U26.10(AGND) U26.18(PGND4) U26.22(PGND3) U26.27(PGND2) U26.36(PGND5) U26.41(PGND1) U26.47(PGND6) U26.52(PGND7) U26.57(GND)
VDD3V3_USB: C156.2 U26.13(LDO4OUT)
VDD_DDR: C39.2 C41.2 C200.2 C202.2 L5.2 LNK8.2 U26.43(LDO3IN)
VDD_DDR_FB: LNK8.1 U26.46(VOUT6)
VDD_EMMC: C190.1 U26.16(LDO2OUT)
VDD_SDCARD: C142.1 U26.4(LDO7OUT)
VDDA1V8_AON: C189.2 U26.14(LDO1OUT)
VDDCORE: C22.2 C23.2 C24.2 C183.2 L2.2 LNK2.2
VDDCORE_FB: LNK2.1 U26.28(VOUT2)
VDDCPU: C26.2 C27.2 C28.2 L3.2 LNK4.1
VDDCPU_FB: LNK4.2 U26.42(VOUT1)
VDDGPU: C34.2 C35.2 C36.2 C37.2 L4.2 LNK7.2
VDDGPU_FB: LNK7.1 U26.21(VOUT3)
VDDIO: C19.2 C186.2 C187.2 L6.2 LNK11.2 U26.29(VIO)
VDDIO_FB: LNK11.1 U26.17(VOUT4)
VDDIO_SDCARD: C217.1 U26.2(LDO8OUT)
VPP_DDR: C91.1 U26.7(LDO5OUT)
VTT_DDR: C40.2 U26.44(LDO3OUT)
I2C7.SCL: U26.33(SCL) ; port I2C7.SCL
I2C7.SDA: U26.34(SDA) ; port I2C7.SDA
MP257_WAKEUP: U26.32(INTn) ; port MP257_WAKEUP
NRST: R81.1 ; port NRST
NRSTC1MS: R59.1 ; port NRSTC1MS
PMIC_WAKEUPn: R46.1 ; port PMIC_WAKEUPn
PWR_CPU_ON: R60.1 ; port PWR_CPU_ON
PWR_ON: R2.1 ; port PWR_ON
NetB2_2: B2.2 C155.2 U26.1(PONKEYn)
NetC43_2: C43.2 U26.45(REFDDR)
NetC208_1: C208.1 U26.8(INTLDO)
NetL1_1: L1.1 U26.37(VLX5)
NetL2_1: L2.1 U26.26(VLX2)
NetL3_1: L3.1 U26.40(VLX1)
NetL4_1: L4.1 U26.23(VLX3)
NetL5_1: L5.1 U26.48(VLX6)
NetL6_1: L6.1 U26.19(VLX4)
NetL7_1: L7.1 U26.51(VLX7)
NetLD11_1: LD11.1 R210.2
NetR2_2: R2.2 U26.56(PWRCTRL1)
NetR46_2: R46.2 U26.30(WAKEUPn)
NetR57_2: R57.2 U26.12(VBUS)
NetR59_2: R59.2 U26.54(PWRCTRL3)
NetR60_2: R60.2 U26.55(PWRCTRL2)
NetR81_2: R81.2 U26.31(RSTn)

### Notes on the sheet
- 5.2V
- 670mV/ 800mV/ 910mV
- (near C24) 670mV/ 820mV
- 800mV/ 900mV
- 3V3
- (near L1) 3V3
- Unused
- 1.2V
- 0.6V
- 2.5V
- 3V3 / 1V8
- (near B2) WAKE UP

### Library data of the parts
B2 = MCD-03492: Switch tactile, SPST-NO, 50mA, 12V, 6x3.8mm; Part_Type: Misc; Part_Preference: Recommended; Manufacturer: WURTH ELEKTRONIC; Component_Country_Of_Origin: China°; ShowFields: YES; ID: 5608
C18 C42 = MCD-01796: Capacitor, Tantalum, 100uF, 6V3, 40mR, +/-20%,  Type_B (3528 metric), T=1.9mm; Part_Preference: Recommended; Manufacturer: AVX; Manufacturer_Part_Number: TCJB107M006R0040; Component_Country_Of_Origin: Lanskroun; ShowFields: YES; ID: 3896
C19 C21 C152 C157 C186 C187 C193 C204 C206 C207 = MCD-03139: Capacitor, MLCC, 22uF, 10V, X5R, +/-20%, 0805, T=1,25mm; Part_Preference: Recommended; Manufacturer: MURATA; Manufacturer_Part_Number: GRM21BR61A226ME51L; ShowFields: YES; ID: 5255; Component_Country_Of_Origin: China, Japan
C20 C29 C30 C32 C38 C184 C199 = MCD-00099: Capacitor, MLCC, 10uF, 10V, X5R, +/-10%, 0603, T=0,8mm; Manufacturer_Part_Number: GRM188R61A106KE69D; Manufacturer: MURATA; Part_Preference: Recommended; Order_Code_RS: 170-6168; Component_Country_Of_Origin: Japan; ID: 2770; ShowFields: YES
C22-C24 C26 C34-C37 C41 C200 C202 = MCD-00100: Capacitor, MLCC, 22uF, 6V3, X5R, +/-20%, 0603, T=0,8mm; Manufacturer_Part_Number: GRM188R60J226MEA0J; Manufacturer: MURATA; Part_Preference: Recommended; Component_Country_Of_Origin: Japan; ID: 2766; ShowFields: YES
C27 C28 C183 = MCD-00100: Capacitor, MLCC, 22uF, 6V3, X5R, +/-20%, 0603, T=0,8mm; Part_Preference: Recommended; Manufacturer: MURATA; Manufacturer_Part_Number: GRM188R60J226MEA0J; Component_Country_Of_Origin: Japan; ID: 2766; ShowFields: YES
C39 = MCD-03140: Capacitor, MLCC, 10uF, 6.3V, X5R, +/-20%, 0402, T=0.5mm; Part_Preference: Recommended; Manufacturer: MURATA; Manufacturer_Part_Number: GRM155R60J106ME05D; ShowFields: YES; ID: 5256
C40 = MCD-03140: Capacitor, MLCC, 10uF, 6.3V, X5R, +/-20%, 0402, T=0.5mm; Part_Preference: Recommended; Manufacturer: MURATA; Manufacturer_Part_Number: GRM155R60J106ME05D; ShowFields: YES; ID: 5256; Component_Country_Of_Origin: China, Japan
C43 C153 C154 C188 = MCD-00095: Capacitor, MLCC, 1uF, 25V, X5R, +/-10%, 0402, T=0.5mm; Part_Preference: Recommended; Manufacturer: MURATA; Manufacturer_Part_Number: GRM155R61E105KA12; Order_Code_RS: 846-7287; Component_Country_Of_Origin: Japan; ShowFields: YES; ID: 2772
C91 C141 C142 C156 C189 C190 C208 C209 C217 = MCD-01356: Capacitor, MLCC, 4.7uF, 6V3, X5R, +/-20%, 0402, T=0.5mm; Manufacturer_Part_Number: GRM155R60J475ME47; Manufacturer: MURATA; Part_Preference: Recommended; Order_Code_RS: 814-5230; Component_Country_Of_Origin: Japan; ShowFields: YES; ID: 3456
C155 = MCD-02198: Capacitor, MLCC, 10nF, 50V, X7R, +/-10%, 0402, T=0.5mm; Manufacturer_Part_Number: CC0402KRX7R9BB103; Manufacturer: YAGEO; Part_Preference: Recommended; Order_Code_RS: 6169644; Component_Country_Of_Origin: China; ShowFields: YES; ID: 4298
L1 L6 = MCD-03143: Inductor, 2.2uH, +/-20%, Itemp= 1700mA, Isat= 2400mA, 0R140, 0806, T=1mm; Part_Preference: Recommended; Manufacturer: MURATA; Manufacturer_Part_Number: DFE201610E-2R2M=P2; ShowFields: YES; ID: 5259; Component_Country_Of_Origin: Vietnam
L2 L4 = MCD-03142: Inductor, 0.68uH, +/-20%, Itemp= 3900mA, Isat= 5400mA, 0R031, 1008, T=1.2mm; Part_Preference: Recommended; Manufacturer: MURATA; Manufacturer_Part_Number: DFE252012F-R68M=P2; ShowFields: YES; ID: 5258; Component_Country_Of_Origin: Vietnam
L3 L5 L7 = MCD-03141: Inductor, 0.68uH, +/-20%, Itemp= 3100mA, Isat= 4300mA, 0R043, 0806, T=1mm; Part_Preference: Recommended; Manufacturer: MURATA; Manufacturer_Part_Number: DFE201610E-R68M=P2; ShowFields: YES; ID: 5257; Component_Country_Of_Origin: Vietnam
LD11 = MCD-00588: LED Green, 0603 SMD, Forward Voltage Typ=2V, Max=2.5V; Part_Type: Display; Manufacturer_Part_Number: LG Q396-PS-35; Manufacturer: OSRAM OPTO SEMICONDUCTORS; Alternate_Manufacturer_Part_Number: VLMTG1300-GS08; Alternate_Manufacturer: VISHAY SEMICONDUCTOR OPTO DIVISION; Alternate_Internal_Part_Number: MCD-02400; Part_Preference: Recommended; Provided_By: SUBCO; Component_Country_Of_Origin: Unknown; ID: 3155; ShowFields: YES
LNK1 LNK2 LNK4 LNK7 LNK8 LNK11 = MCD-02777: Track link on PCB 200um width for layout routing; Part_Preference: Recommended; Part_Type: Misc; ID: 4889; ShowFields: YES
R2 R46 R57 R59 R60 R81 = MCD-00052: Resistor,0R,0402,5%,1/16W; Manufacturer_Part_Number: RC0402JR-070RL; Manufacturer: YAGEO; Part_Preference: Recommended; ECCN_US: EAR99; ECCN_EU: NEC; Provided_By: SUBCO; Initial_Board_Reference: mb1274; Order_Code_RS: 618-5804; Component_Country_Of_Origin: China; ID: 2540; ShowFields: YES
R210 = MCD-00441: Resistor,270R,0402,1%,1/16W; Manufacturer_Part_Number: RC0402FR-07270RL; Manufacturer: YAGEO; Part_Preference: Recommended; Provided_By: SUBCO; ECCN_US: EAR99; ECCN_EU: NEC; Component_Country_Of_Origin: China; ID: 2838; ShowFields: YES
U26 = MCD-03000: STPMIC2; Part_Type: IC; Part_Preference: Recommended; Manufacturer: STMICROELECTRONICS; Component_Country_Of_Origin: Unknown; ShowFields: YES; ID: 5116

## Sheet STM32MP25XXAL Power.SchDoc: STM32MP25XXAL Power
size A3; Date: Not used; ApprovedBy: Not used; CheckedBy: Not used; Author: Not used; CompanyName: STMicroelectronics; DrawnBy: Not used; Engineer: Not used; Organization: Not used; Address1: Not used; Address2: Not used; Address3: Not used; Address4: Not used; DocumentNumber: 5; Revision: Not used; SheetNumber: 5; SheetTotal: 7
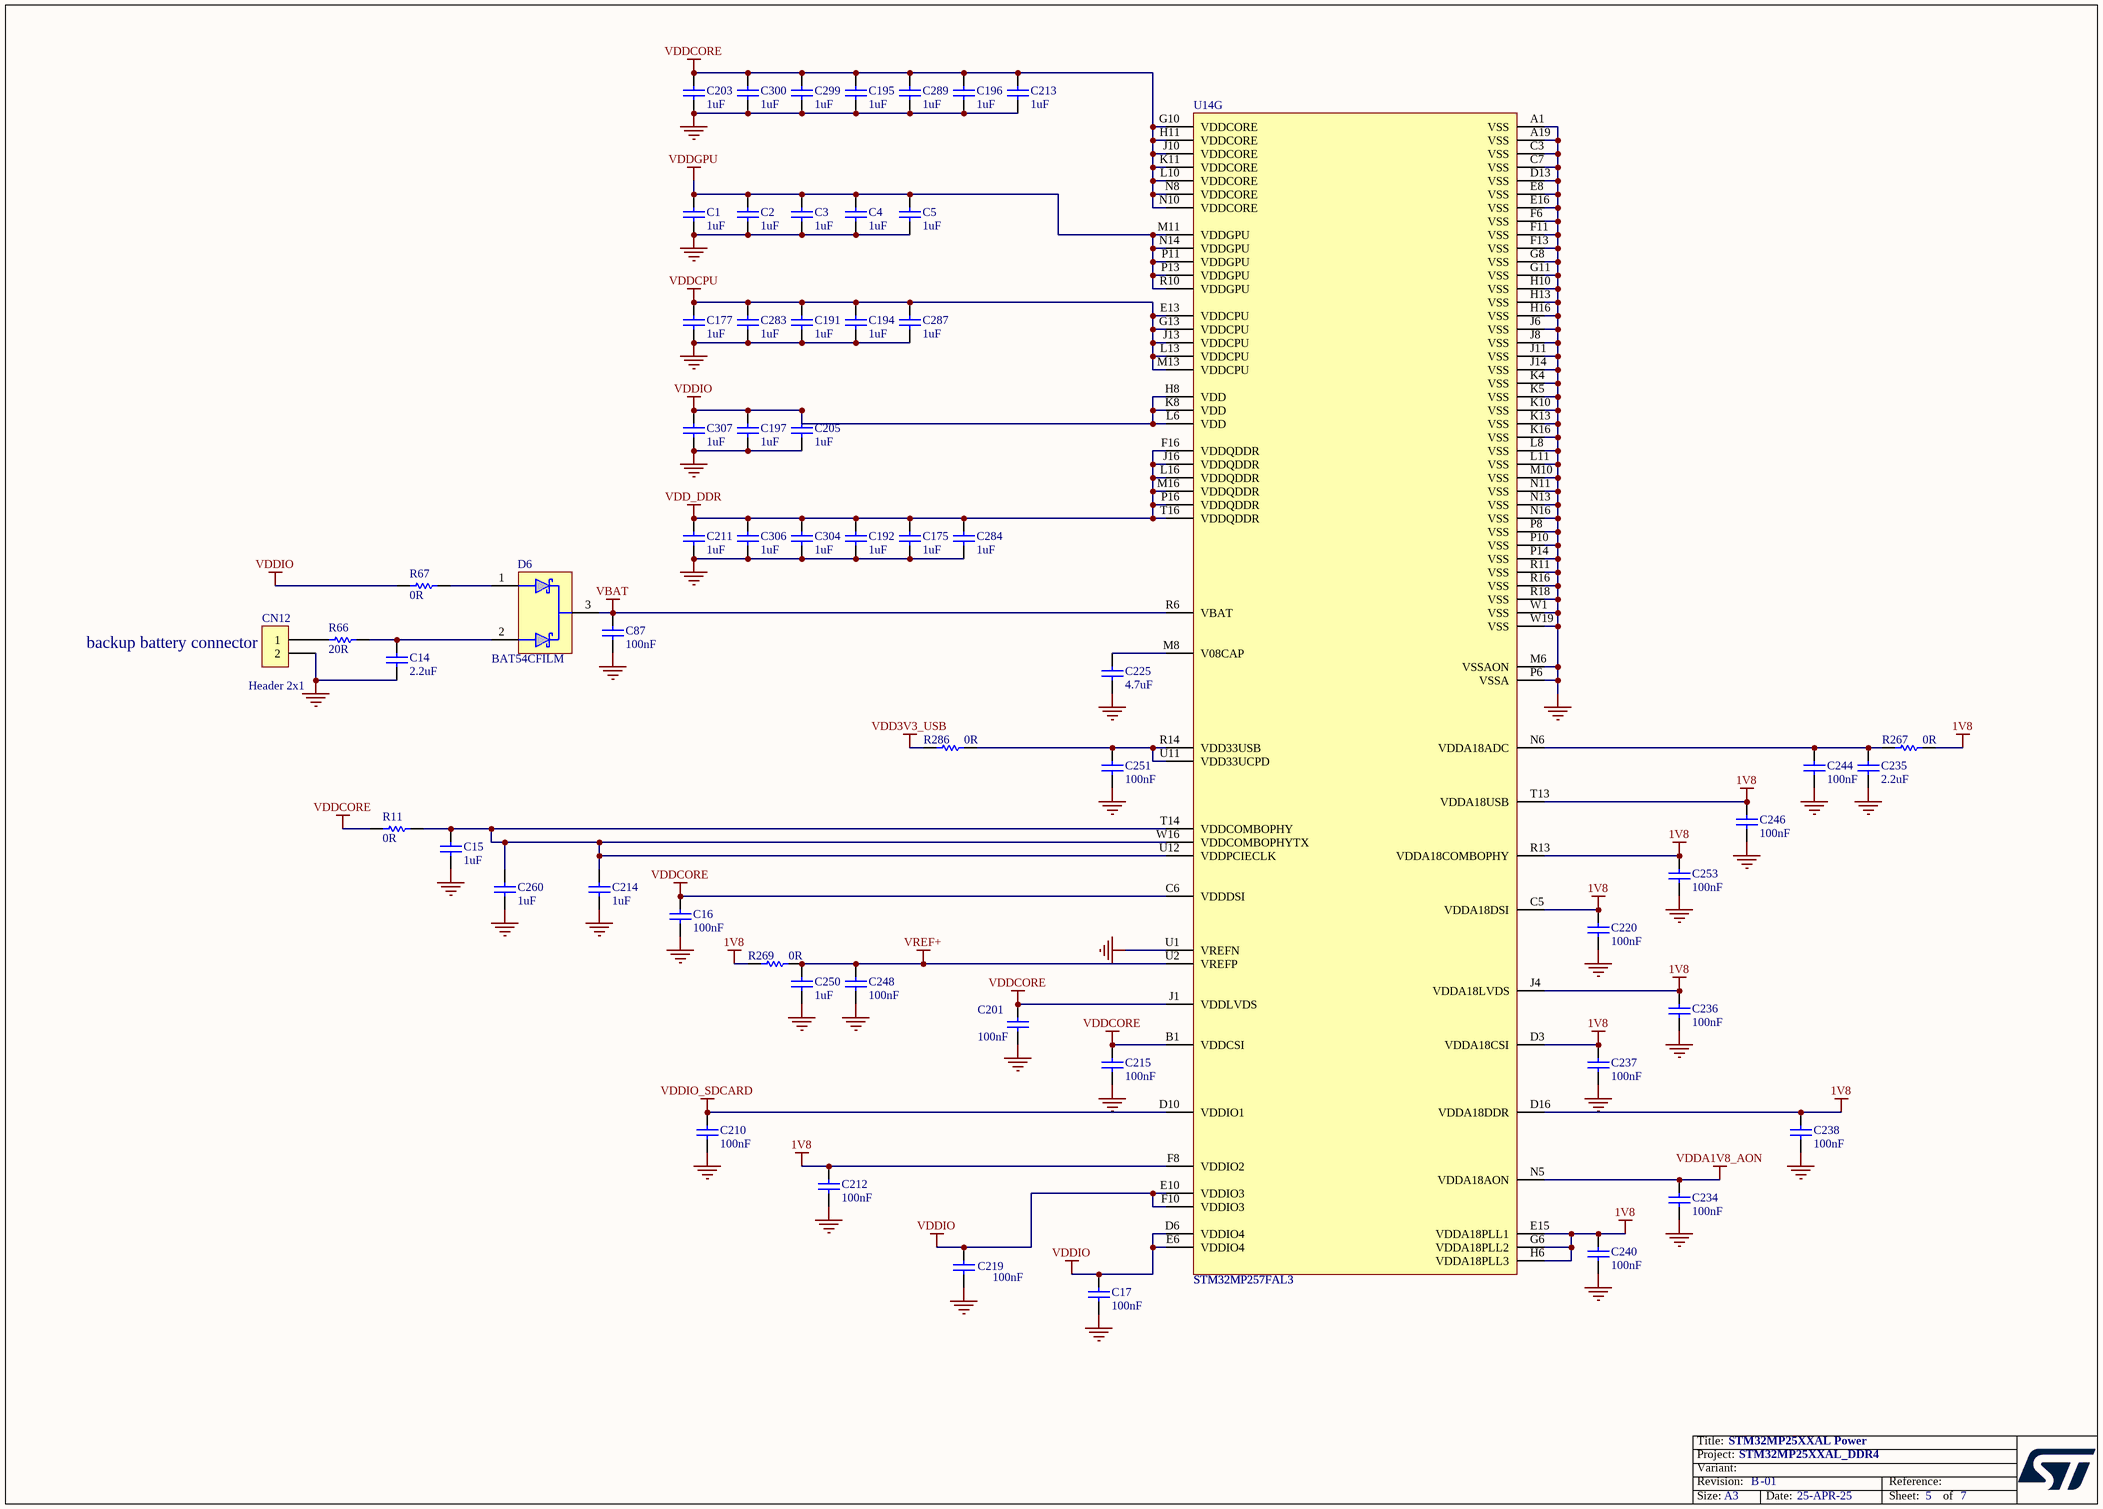
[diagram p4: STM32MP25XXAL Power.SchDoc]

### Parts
C1  1uF  [C0201_MURATA_GRM033_H0P3]
C2  1uF  [C0201_MURATA_GRM033_H0P3]
C3  1uF  [C0201_MURATA_GRM033_H0P3]
C4  1uF  [C0201_MURATA_GRM033_H0P3]
C5  1uF  [C0201_MURATA_GRM033_H0P3]
C14  value 2.2uF  [C0402]  (hidden comment: Capacitor)
C15  value 1uF  [C0201_MURATA_GRM033_H0P3]  (hidden comment: Capacitor)
C16  value 100nF  [C0201_MURATA_GRM033_H0P3]  (hidden comment: Capacitor)
C17  value 100nF  [C0201_MURATA_GRM033_H0P3]  (hidden comment: Capacitor)
C87  value 100nF  [C0402]
C175  value 1uF  [C0201_MURATA_GRM033_H0P3]  (hidden comment: Capacitor)
C177  value 1uF  [C0201_MURATA_GRM033_H0P3]  (hidden comment: Capacitor)
C191  value 1uF  [C0201_MURATA_GRM033_H0P3]  (hidden comment: Capacitor)
C192  value 1uF  [C0201_MURATA_GRM033_H0P3]  (hidden comment: Capacitor)
C194  value 1uF  [C0201_MURATA_GRM033_H0P3]  (hidden comment: Capacitor)
C195  value 1uF  [C0201_MURATA_GRM033_H0P3]  (hidden comment: Capacitor)
C196  value 1uF  [C0201_MURATA_GRM033_H0P3]  (hidden comment: Capacitor)
C197  value 1uF  [C0201_MURATA_GRM033_H0P3]  (hidden comment: Capacitor)
C201  value 100nF  [C0201_MURATA_GRM033_H0P3]  (hidden comment: Capacitor)
C203  value 1uF  [C0201_MURATA_GRM033_H0P3]  (hidden comment: Capacitor)
C205  value 1uF  [C0201_MURATA_GRM033_H0P3]  (hidden comment: Capacitor)
C210  value 100nF  [C0201_MURATA_GRM033_H0P3]  (hidden comment: Capacitor)
C211  value 1uF  [C0201_MURATA_GRM033_H0P3]  (hidden comment: Capacitor)
C212  value 100nF  [C0201_MURATA_GRM033_H0P3]  (hidden comment: Capacitor)
C213  value 1uF  [C0201_MURATA_GRM033_H0P3]  (hidden comment: Capacitor)
C214  value 1uF  [C0201_MURATA_GRM033_H0P3]  (hidden comment: Capacitor)
C215  value 100nF  [C0201_MURATA_GRM033_H0P3]  (hidden comment: Capacitor)
C219  value 100nF  [C0201_MURATA_GRM033_H0P3]  (hidden comment: Capacitor)
C220  value 100nF  [C0201_MURATA_GRM033_H0P3]  (hidden comment: Capacitor)
C225  value 4.7uF  [C0201_H0P5]  (hidden comment: Capacitor)
C234  value 100nF  [C0201_MURATA_GRM033_H0P3]  (hidden comment: Capacitor)
C235  value 2.2uF  [C0201_H0P5]  (hidden comment: Capacitor)
C236  value 100nF  [C0201_MURATA_GRM033_H0P3]  (hidden comment: Capacitor)
C237  value 100nF  [C0201_MURATA_GRM033_H0P3]  (hidden comment: Capacitor)
C238  value 100nF  [C0201_MURATA_GRM033_H0P3]  (hidden comment: Capacitor)
C240  value 100nF  [C0201_MURATA_GRM033_H0P3]  (hidden comment: Capacitor)
C244  value 100nF  [C0201_MURATA_GRM033_H0P3]  (hidden comment: Capacitor)
C246  value 100nF  [C0201_MURATA_GRM033_H0P3]  (hidden comment: Capacitor)
C248  value 100nF  [C0201_MURATA_GRM033_H0P3]  (hidden comment: Capacitor)
C250  value 1uF  [C0201_MURATA_GRM033_H0P3]  (hidden comment: Capacitor)
C251  value 100nF  [C0201_MURATA_GRM033_H0P3]  (hidden comment: Capacitor)
C253  value 100nF  [C0201_MURATA_GRM033_H0P3]  (hidden comment: Capacitor)
C260  value 1uF  [C0201_MURATA_GRM033_H0P3]  (hidden comment: Capacitor)
C283  value 1uF  [C0201_MURATA_GRM033_H0P3]  (hidden comment: Capacitor)
C284  value 1uF  [C0201_MURATA_GRM033_H0P3]  (hidden comment: Capacitor)
C287  value 1uF  [C0201_MURATA_GRM033_H0P3]  (hidden comment: Capacitor)
C289  value 1uF  [C0201_MURATA_GRM033_H0P3]  (hidden comment: Capacitor)
C299  value 1uF  [C0201_MURATA_GRM033_H0P3]  (hidden comment: Capacitor)
C300  value 1uF  [C0201_MURATA_GRM033_H0P3]  (hidden comment: Capacitor)
C304  value 1uF  [C0201_MURATA_GRM033_H0P3]  (hidden comment: Capacitor)
C306  value 1uF  [C0201_MURATA_GRM033_H0P3]  (hidden comment: Capacitor)
C307  value 1uF  [C0201_MURATA_GRM033_H0P3]  (hidden comment: Capacitor)
CN12  value Header 2x1  [CON_MOLEX_53047-0210]
D6  value BAT54CFILM  [DIO_SOT23]  (hidden comment: DIODE_3P_DUAL_COMMON_CATHODE)
R11  value 0R  [R0603]  (hidden comment: Resistor)
R66  value 20R  [R0402]  (hidden comment: Resistor)
R67  value 0R  [R0402]  (hidden comment: Resistor)
R267  value 0R  [R0402]
R269  value 0R  [R0402]
R286  value 0R  [R0402]
U14  STM32MP257FAL3  [ICC_VFBGA361_10X10_P050]  (part G of 8)

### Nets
1V8: C212.2 C220.2 C236.2 C237.2 C238.2 C240.2 C246.2 C253.2 R267.2 R269.1 U14.C5(VDDA18DSI) U14.D3(VDDA18CSI) U14.D16(VDDA18DDR) U14.E15(VDDA18PLL1) U14.F8(VDDIO2) U14.G6(VDDA18PLL2) U14.H6(VDDA18PLL3) U14.J4(VDDA18LVDS) U14.R13(VDDA18COMBOPHY) U14.T13(VDDA18USB)
GND: C1.1 C2.1 C3.1 C4.1 C5.1 C14.1 C15.1 C16.1 C17.1 C87.1 C175.2 C177.2 C191.2 C192.2 C194.1 C195.2 C196.1 C197.1 C201.1 C203.2 C205.1 C210.1 C211.2 C212.1 C213.1 C214.1 C215.1 C219.1 C220.1 C225.1 C234.1 C235.1 C236.1 C237.1 C238.1 C240.1 C244.1 C246.1 C248.1 C250.1 C251.1 C253.1 C260.1 C283.1 C284.2 C287.1 C289.1 C299.1 C300.1 C304.2 C306.2 C307.2 CN12.2 U14.A1(VSS) U14.A19(VSS) U14.C3(VSS) U14.C7(VSS) U14.D13(VSS) U14.E8(VSS) U14.E16(VSS) U14.F6(VSS) U14.F11(VSS) U14.F13(VSS) U14.G8(VSS) U14.G11(VSS) U14.H10(VSS) U14.H13(VSS) U14.H16(VSS) U14.J6(VSS) U14.J8(VSS) U14.J11(VSS) U14.J14(VSS) U14.K4(VSS) U14.K5(VSS) U14.K10(VSS) U14.K13(VSS) U14.K16(VSS) U14.L8(VSS) U14.L11(VSS) U14.M6(VSSAON) U14.M10(VSS) U14.N11(VSS) U14.N13(VSS) U14.N16(VSS) U14.P6(VSSA) U14.P8(VSS) U14.P10(VSS) U14.P14(VSS) U14.R11(VSS) U14.R16(VSS) U14.R18(VSS) U14.U1(VREFN) U14.W1(VSS) U14.W19(VSS)
VBAT: C87.2 D6.3 U14.R6(VBAT)
VDD3V3_USB: R286.1
VDD_DDR: C175.1 C192.1 C211.1 C284.1 C304.1 C306.1 U14.F16(VDDQDDR) U14.J16(VDDQDDR) U14.L16(VDDQDDR) U14.M16(VDDQDDR) U14.P16(VDDQDDR) U14.T16(VDDQDDR)
VDDA1V8_AON: C234.2 U14.N5(VDDA18AON)
VDDCORE: C16.2 C195.1 C196.2 C201.2 C203.1 C213.2 C215.2 C289.2 C299.2 C300.2 R11.1 U14.B1(VDDCSI) U14.C6(VDDDSI) U14.G10(VDDCORE) U14.H11(VDDCORE) U14.J1(VDDLVDS) U14.J10(VDDCORE) U14.K11(VDDCORE) U14.L10(VDDCORE) U14.N8(VDDCORE) U14.N10(VDDCORE)
VDDCPU: C177.1 C191.1 C194.2 C283.2 C287.2 U14.E13(VDDCPU) U14.G13(VDDCPU) U14.J13(VDDCPU) U14.L13(VDDCPU) U14.M13(VDDCPU)
VDDGPU: C1.2 C2.2 C3.2 C4.2 C5.2 U14.M11(VDDGPU) U14.N14(VDDGPU) U14.P11(VDDGPU) U14.P13(VDDGPU) U14.R10(VDDGPU)
VDDIO: C17.2 C197.2 C205.2 C219.2 C307.1 R67.2 U14.D6(VDDIO4) U14.E6(VDDIO4) U14.E10(VDDIO3) U14.F10(VDDIO3) U14.H8(VDD) U14.K8(VDD) U14.L6(VDD)
VDDIO_SDCARD: C210.2 U14.D10(VDDIO1)
VREF+: C248.2 C250.2 R269.2 U14.U2(VREFP)
NetC14_2: C14.2 D6.2 R66.2
NetC15_2: C15.2 C214.2 C260.2 R11.2 U14.T14(VDDCOMBOPHY) U14.U12(VDDPCIECLK) U14.W16(VDDCOMBOPHYTX)
NetC225_2: C225.2 U14.M8(V08CAP)
NetC235_2: C235.2 C244.2 R267.1 U14.N6(VDDA18ADC)
NetC251_2: C251.2 R286.2 U14.R14(VDD33USB) U14.U11(VDD33UCPD)
NetCN12_1: CN12.1 R66.1
NetD6_1: D6.1 R67.1

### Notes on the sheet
- (near CN12) backup battery connector

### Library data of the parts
C1-C5 = MCD-02377: Capacitor, MLCC, 1uF, 6.3V, X5R, +/-20%, 0201, T=0,3mm; Part_Preference: Recommended; Manufacturer: MURATA; Manufacturer_Part_Number: GRM033R60J105MEA2; Order_Code_RS: 820-0643; Component_Country_Of_Origin: Japan; ShowFields: YES; ID: 4483
C14 = MCD-01823: Capacitor, MLCC, 2.2uF, 6V3, X5R,+/-10%, 0402, T=0.5mm; Part_Preference: Recommended; Manufacturer: MURATA; Manufacturer_Part_Number: GRM155R60J225KE95D; Order_Code_RS: 172-6478; Component_Country_Of_Origin: Japan; ID: 3923; ShowFields: YES
C15 C214 C250 C260 = MCD-02377: Capacitor, MLCC, 1uF, 6.3V, X5R, +/-20%, 0201, T=0,3mm; Manufacturer_Part_Number: GRM033R60J105MEA2; Manufacturer: MURATA; Part_Preference: Recommended; Order_Code_RS: 820-0643; Component_Country_Of_Origin: Japan; ID: 4483; ShowFields: YES
C16 C17 C201 C210 C212 C215 C219 C220 C234 C236-C238 C240 C244 C246 C248 C251 C253 = MCD-01535: Capacitor, MLCC,100nF, 10V, X7R, +/-10%, 0201, T=0.3mm; Part_Preference: Recommended; Manufacturer: MURATA; Manufacturer_Part_Number: GRM033R61A104KE15; Order_Code_RS: 790-2742; Component_Country_Of_Origin: Japan; ID: 3635; ShowFields: YES
C87 = MCD-00006: Capacitor,100nF,16V,X7R,10%,0402; Manufacturer_Part_Number: CC0402KRX7R7BB104; Manufacturer: YAGEO; Alternate_Manufacturer: MURATA; Alternate_Manufacturer_Part_Number: GCM155R71C104KA55D; Part_Preference: Recommended; Partial_Alternate_Internal_Part_Number: MCD-03299; Provided_By: SUBCO; Initial_Board_Reference: MB1274; Order_Code_RS: 616-9701; Component_Country_Of_Origin: China; ID: 2474; ShowFields: YES; Alternate_EMS: M
C175 C177 C191 C192 C194-C197 C203 C205 C211 C213 C283 C284 C287 C289 C299 C300 C304 C306 C307 = MCD-01533: Capacitor, MLCC, 1uF, 6V3, X5R, +/-20%, 0201,T=0.3mm; Part_Preference: Not recommended; Manufacturer: MURATA; Manufacturer_Part_Number: GRM033R60J105ME11; Alternate_Manufacturer_Part_Number: GRM033R60J105MEA2
C225 = MCD-01534: Capacitor, MLCC, 4,7uF, 6V3, X5R, +/-20%, 0201, T=0.5mm; Part_Preference: Recommended; Manufacturer: MURATA; Manufacturer_Part_Number: GRM035R60J475ME15; Component_Country_Of_Origin: Japan; ID: 3634; ShowFields: YES
C235 = MCD-02235: Capacitor, MLCC, 2.2uF, 10V, X5R,+/-10%, 0201, T=0.5mm; Part_Preference: Recommended; Manufacturer: MURATA; Manufacturer_Part_Number: GRM033R61A225KE47D; Order_Code_RS: NA; Component_Country_Of_Origin: Japan; ShowFields: YES; ID: 4335
CN12 = MCD-00655: Header 2 circuits, 1.25mm Pitch ,  Vertical, with Friction Lock; Part_Type: Connector; Manufacturer_Part_Number: 53047-0210; Manufacturer: MOLEX; BMS_Part_Number: 9083002; Part_Preference: Recommended; Provided_By: SUBCO; Initial_Board_Reference: MB1272; Order_Code_RS: 279-9213; Component_Country_Of_Origin: Unknown; ID: 3091; ShowFields: YES
D6 = MCD-03280: Diode, Schottky, Dual Common Cathode, 0V3, 300mA, 40V, SOT-23; Part_Preference: Recommended; Manufacturer: STMICROELECTRONICS; Full_Alternate_Internal_Part_Number: BAT54C+, BAT54CLT1G, BAT54C-7-F, BAT54C,215; Order_code_RS: 795-8397; Component_Country_Of_Origin: China; ShowFields: YES; ID: 5396
R11 = MCD-00056: Resistor, 0R, 0603, +/-5%, 1/10W; Part_Preference: Recommended; Manufacturer: YAGEO; Manufacturer_Part_Number: RC0603JR-070RL; Component_Country_Of_Origin: China; ShowFields: YES; ID: 2536
R66 = MCD-00058: Resistor, 20R, 0402, +/-1%, 1/16W; BMS_Part_Number: 9131027; Part_Preference: Recommended; Manufacturer: YAGEO; Manufacturer_Part_Number: RC0402FR-0720RL; Component_Country_Of_Origin: China; ID: 2537; ShowFields: YES
R67 = MCD-00052: Resistor, 0R, 0402, +/-5%, 1/16W; Manufacturer_Part_Number: RC0402JR-070RL; Manufacturer: YAGEO; Part_Preference: Recommended; Order_Code_RS: 618-5804; Component_Country_Of_Origin: China; ShowFields: YES; ID: 2540
R267 R269 R286 = MCD-00052: as R2 on sheet PMIC
U14 = MCD-03768: as U14 on sheet STM32MP25XXAL I_Os

## Sheet eMMC.SchDoc: eMMC
size A3; Date: Not used; ApprovedBy: Not used; CheckedBy: Not used; Author: Not used; CompanyName: STMicroelectronics; DrawnBy: Not used; Engineer: Not used; Organization: Not used; Address1: Not used; Address2: Not used; Address3: Not used; Address4: Not used; DocumentNumber: 7; Revision: Not used; SheetNumber: 7; SheetTotal: 7
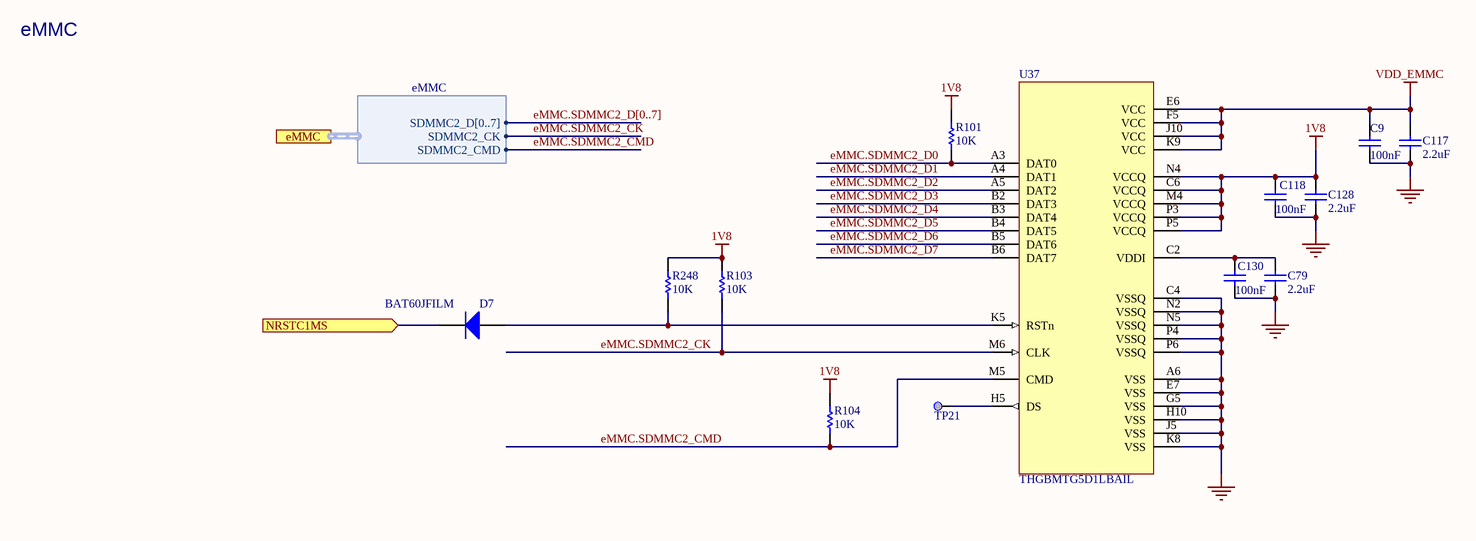
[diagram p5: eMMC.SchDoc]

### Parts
C9  value 100nF  [C0402]  (hidden comment: Capacitor)
C79  value 2.2uF  [C0402]  (hidden comment: Capacitor)
C117  value 2.2uF  [C0402]  (hidden comment: Capacitor)
C118  value 100nF  [C0402]  (hidden comment: Capacitor)
C128  value 2.2uF  [C0402]  (hidden comment: Capacitor)
C130  value 100nF  [C0402]  (hidden comment: Capacitor)
D7  BAT60JFILM  [DIO_SOD323]
R101  value 10K  [R0402]  (hidden comment: Resistor)
R103  value 10K  [R0402]  (hidden comment: Resistor)
R104  value 10K  [R0402]  (hidden comment: Resistor)
R248  value 10K  [R0402]  (hidden comment: Resistor)
TP21  Test Point  [TP_SMD_1MM]  (value not drawn)  (no BOM)
U37  value THGBMTG5D1LBAIL  [ICC_P-WFBGA153_13X11P5_P050]  (hidden comment: eMMC_THGBMTG5D1LBAIL)

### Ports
eMMC (harness eMMC), NRSTC1MS (in)

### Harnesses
eMMC: SDMMC2_CK, SDMMC2_CMD, SDMMC2_D[0..7]

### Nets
1V8: C118.2 C128.2 R101.2 R103.2 R104.2 R248.2 U37.C6(VCCQ) U37.M4(VCCQ) U37.N4(VCCQ) U37.P3(VCCQ) U37.P5(VCCQ)
GND: C9.1 C79.1 C117.1 C118.1 C128.1 C130.1 U37.A6(VSS) U37.C4(VSSQ) U37.E7(VSS) U37.G5(VSS) U37.H10(VSS) U37.J5(VSS) U37.K8(VSS) U37.N2(VSSQ) U37.N5(VSSQ) U37.P4(VSSQ) U37.P6(VSSQ)
VDD_EMMC: C9.2 C117.2 U37.E6(VCC) U37.F5(VCC) U37.J10(VCC) U37.K9(VCC)
eMMC.SDMMC2_CK: R103.1 U37.M6(CLK) ; port eMMC.SDMMC2_CK
eMMC.SDMMC2_CMD: R104.1 U37.M5(CMD) ; port eMMC.SDMMC2_CMD
eMMC.SDMMC2_D0: R101.1 U37.A3(DAT0)
eMMC.SDMMC2_D1: U37.A4(DAT1)
eMMC.SDMMC2_D2: U37.A5(DAT2)
eMMC.SDMMC2_D3: U37.B2(DAT3)
eMMC.SDMMC2_D4: U37.B3(DAT4)
eMMC.SDMMC2_D5: U37.B4(DAT5)
eMMC.SDMMC2_D6: U37.B5(DAT6)
eMMC.SDMMC2_D7: U37.B6(DAT7)
NRSTC1MS: D7.2(K) ; port NRSTC1MS
NetC79_2: C79.2 C130.2 U37.C2(VDDI)
NetD7_1: D7.1(A) R248.1 U37.K5(RSTn)
NetTP21_1: TP21.1 U37.H5(DS)

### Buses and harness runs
bus eMMC.SDMMC2_D[0..7]

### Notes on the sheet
- eMMC

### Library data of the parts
C9 C118 C130 = MCD-00006: Capacitor, MLCC, 100nF, 16V, X7R, +/-10%, 0402, T=0.5mm; Part_Preference: Recommended; Manufacturer: YAGEO; Manufacturer_Part_Number: CC0402KRX7R7BB104; Alternate_Manufacturer: MURATA; Alternate_Manufacturer_Part_Number: GCM155R71C104KA55D; Partial_Alternate_Internal_Part_Number: MCD-03299; Order_Code_RS: 616-9701; Component_Country_Of_Origin: China; Alternate_EMS: M; ID: 2474; ShowFields: YES
C79 C117 C128 = MCD-02606: Capacitor, MLCC, 2.2uF, 6.3V, X5R, +/-10%, 0402, T=0.5mm; Part_Preference: Recommended; Manufacturer: YAGEO; Manufacturer_Part_Number: CC0402KRX5R5BB225; Order_Code_RS: 1992205; ShowFields: YES; ID: 4712; Component_Country_Of_Origin: China°
D7 = MCD-00034: BMS_Part_Number: 9151097; Part_Type: Diode; Part_Preference: Recommended; Manufacturer: STMICROELECTRONICS; Manufacturer_HQ_COO: EU; Component_Country_Of_Origin: China; ShowFields: YES; ID: 2483
R101 R103 R104 R248 = MCD-00053: Resistor,10K,0402,1%,1/16W; Manufacturer_Part_Number: RC0402FR-0710KL; Manufacturer: YAGEO; BMS_Part_Number: 9131590; Part_Preference: Recommended; ECCN_US: EAR99; ECCN_EU: NEC; Provided_By: SUBCO; Component_Country_Of_Origin: China; ID: 2539; ShowFields: YES
TP21 = MCD-00074: Test Point 1mm; Part_Type: Misc; Part_Preference: Recommended; ID: 2518; ShowFields: YES
U37 = MCD-02799: Memory, eMMC, 4GB, 15nm ,WFBGA , 153 pins; Part_Type: IC; Part_Preference: Recommended; Manufacturer: KIOXIA; ShowFields: YES; ID: 4911; Component_Country_Of_Origin: Unknown

## Sheet DDR4_16bits.SchDoc: DDR4_16bits
size A3; Date: Not used; ApprovedBy: Not used; CheckedBy: Not used; Author: Not used; CompanyName: STMicroelectronics; DrawnBy: Not used; Engineer: Not used; Organization: Not used; Address1: Not used; Address2: Not used; Address3: Not used; Address4: Not used; DocumentNumber: 6; Revision: Not used; SheetNumber: 6; SheetTotal: 7
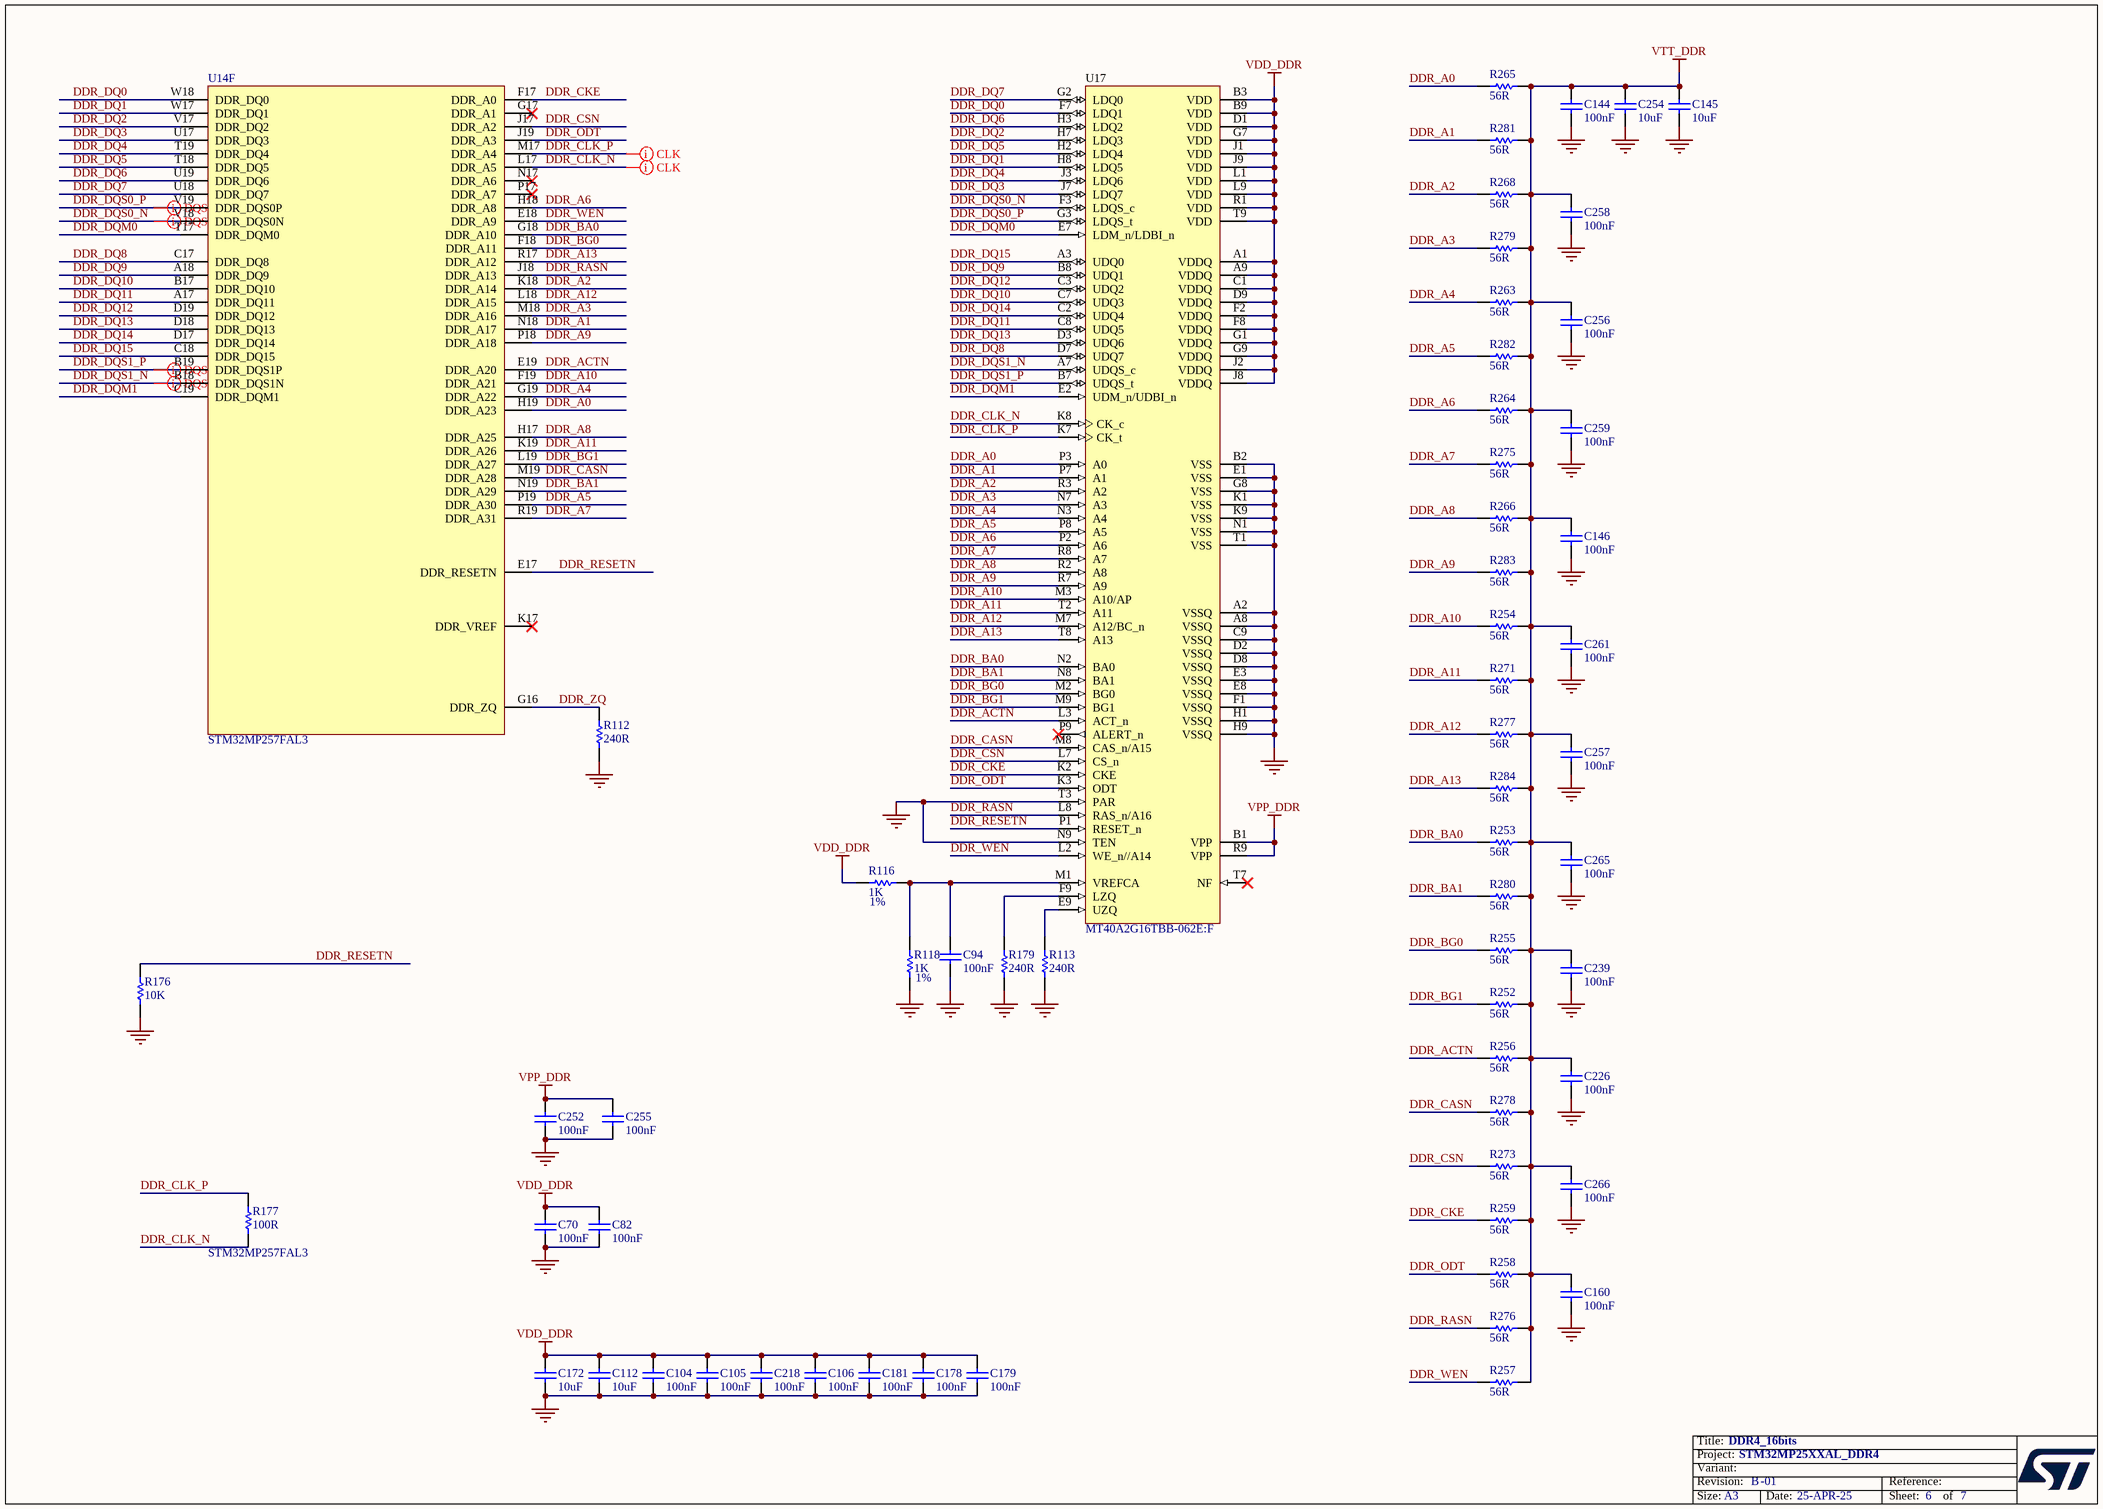
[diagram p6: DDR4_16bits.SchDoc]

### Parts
C70  value 100nF  [C0402]  (hidden comment: Capacitor)
C82  value 100nF  [C0402]  (hidden comment: Capacitor)
C94  value 100nF  [C0402]  (hidden comment: Capacitor)
C104  value 100nF  [C0402]  (hidden comment: Capacitor)
C105  value 100nF  [C0402]  (hidden comment: Capacitor)
C106  value 100nF  [C0402]  (hidden comment: Capacitor)
C112  value 10uF  [C0603]  (hidden comment: Capacitor)
C144  value 100nF  [C0402]  (hidden comment: Capacitor)
C145  value 10uF  [C0402]  (hidden comment: Capacitor)
C146  value 100nF  [C0402]  (hidden comment: Capacitor)
C160  value 100nF  [C0402]  (hidden comment: Capacitor)
C172  value 10uF  [C0603]  (hidden comment: Capacitor)
C178  value 100nF  [C0402]  (hidden comment: Capacitor)
C179  value 100nF  [C0402]  (hidden comment: Capacitor)
C181  value 100nF  [C0402]  (hidden comment: Capacitor)
C218  value 100nF  [C0402]  (hidden comment: Capacitor)
C226  value 100nF  [C0402]  (hidden comment: Capacitor)
C239  value 100nF  [C0402]  (hidden comment: Capacitor)
C252  value 100nF  [C0402]  (hidden comment: Capacitor)
C254  value 10uF  [C0402]  (hidden comment: Capacitor)
C255  value 100nF  [C0402]  (hidden comment: Capacitor)
C256  value 100nF  [C0402]  (hidden comment: Capacitor)
C257  value 100nF  [C0402]  (hidden comment: Capacitor)
C258  value 100nF  [C0402]  (hidden comment: Capacitor)
C259  value 100nF  [C0402]  (hidden comment: Capacitor)
C261  value 100nF  [C0402]  (hidden comment: Capacitor)
C265  value 100nF  [C0402]  (hidden comment: Capacitor)
C266  value 100nF  [C0402]  (hidden comment: Capacitor)
R112  value 240R  [R0201_H0P23]  (hidden comment: Resistor)
R113  value 240R  [R0201_H0P23]  (hidden comment: Resistor)
R116  value 1K  [R0402]  (hidden comment: Resistor)
R118  value 1K  [R0402]  (hidden comment: Resistor)
R176  value 10K  [R0402]  (hidden comment: Resistor)
R177  value 100R  [R0402]  (hidden comment: Resistor)
R179  value 240R  [R0201_H0P23]  (hidden comment: Resistor)
R252  value 56R  [R0402]  (hidden comment: Resistor)
R253  value 56R  [R0402]  (hidden comment: Resistor)
R254  value 56R  [R0402]  (hidden comment: Resistor)
R255  value 56R  [R0402]  (hidden comment: Resistor)
R256  value 56R  [R0402]  (hidden comment: Resistor)
R257  value 56R  [R0402]  (hidden comment: Resistor)
R258  value 56R  [R0402]  (hidden comment: Resistor)
R259  value 56R  [R0402]  (hidden comment: Resistor)
R263  value 56R  [R0402]  (hidden comment: Resistor)
R264  value 56R  [R0402]  (hidden comment: Resistor)
R265  value 56R  [R0402]  (hidden comment: Resistor)
R266  value 56R  [R0402]  (hidden comment: Resistor)
R268  value 56R  [R0402]  (hidden comment: Resistor)
R271  value 56R  [R0402]  (hidden comment: Resistor)
R273  value 56R  [R0402]  (hidden comment: Resistor)
R275  value 56R  [R0402]  (hidden comment: Resistor)
R276  value 56R  [R0402]  (hidden comment: Resistor)
R277  value 56R  [R0402]  (hidden comment: Resistor)
R278  value 56R  [R0402]  (hidden comment: Resistor)
R279  value 56R  [R0402]  (hidden comment: Resistor)
R280  value 56R  [R0402]  (hidden comment: Resistor)
R281  value 56R  [R0402]  (hidden comment: Resistor)
R282  value 56R  [R0402]  (hidden comment: Resistor)
R283  value 56R  [R0402]  (hidden comment: Resistor)
R284  value 56R  [R0402]  (hidden comment: Resistor)
U14  STM32MP257FAL3  [ICC_VFBGA361_10X10_P050]  (part F of 8)
U17  MT40A2G16TBB-062E:F  [ICC_FBGA96_TBB_7P5X13_P080]

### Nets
GND: C70.1 C82.1 C94.1 C104.1 C105.1 C106.1 C112.1 C144.1 C145.1 C146.1 C160.1 C172.1 C178.1 C179.1 C181.1 C218.1 C226.1 C239.1 C252.1 C254.1 C255.1 C256.1 C257.1 C258.1 C259.1 C261.1 C265.1 C266.1 R112.1 R113.1 R118.1 R176.1 R179.1 U17.A2(VSSQ) U17.A8(VSSQ) U17.B2(VSS) U17.C9(VSSQ) U17.D2(VSSQ) U17.D8(VSSQ) U17.E1(VSS) U17.E3(VSSQ) U17.E8(VSSQ) U17.F1(VSSQ) U17.G8(VSS) U17.H1(VSSQ) U17.H9(VSSQ) U17.K1(VSS) U17.K9(VSS) U17.N1(VSS) U17.N9(TEN) U17.T1(VSS) U17.T3(PAR)
VDD_DDR: C70.2 C82.2 C104.2 C105.2 C106.2 C112.2 C172.2 C178.2 C179.2 C181.2 C218.2 R116.1 U17.A1(VDDQ) U17.A9(VDDQ) U17.B3(VDD) U17.B9(VDD) U17.C1(VDDQ) U17.D1(VDD) U17.D9(VDDQ) U17.F2(VDDQ) U17.F8(VDDQ) U17.G1(VDDQ) U17.G7(VDD) U17.G9(VDDQ) U17.J1(VDD) U17.J2(VDDQ) U17.J8(VDDQ) U17.J9(VDD) U17.L1(VDD) U17.L9(VDD) U17.R1(VDD) U17.T9(VDD)
VPP_DDR: C252.2 C255.2 U17.B1(VPP) U17.R9(VPP)
VTT_DDR: C144.2 C145.2 C146.2 C160.2 C226.2 C239.2 C254.2 C256.2 C257.2 C258.2 C259.2 C261.2 C265.2 C266.2 R252.2 R253.2 R254.2 R255.2 R256.2 R257.2 R258.2 R259.2 R263.2 R264.2 R265.2 R266.2 R268.2 R271.2 R273.2 R275.2 R276.2 R277.2 R278.2 R279.2 R280.2 R281.2 R282.2 R283.2 R284.2
DDR_A0: R265.1 U14.H19(DDR_A23) U17.P3(A0)
DDR_A1: R281.1 U14.N18(DDR_A17) U17.P7(A1)
DDR_A2: R268.1 U14.K18(DDR_A14) U17.R3(A2)
DDR_A3: R279.1 U14.M18(DDR_A16) U17.N7(A3)
DDR_A4: R263.1 U14.G19(DDR_A22) U17.N3(A4)
DDR_A5: R282.1 U14.P19(DDR_A30) U17.P8(A5)
DDR_A6: R264.1 U14.H18(DDR_A8) U17.P2(A6)
DDR_A7: R275.1 U14.R19(DDR_A31) U17.R8(A7)
DDR_A8: R266.1 U14.H17(DDR_A25) U17.R2(A8)
DDR_A9: R283.1 U14.P18(DDR_A18) U17.R7(A9)
DDR_A10: R254.1 U14.F19(DDR_A21) U17.M3(A10/AP)
DDR_A11: R271.1 U14.K19(DDR_A26) U17.T2(A11)
DDR_A12: R277.1 U14.L18(DDR_A15) U17.M7(A12/BC_n)
DDR_A13: R284.1 U14.R17(DDR_A12) U17.T8(A13)
DDR_ACTN: R256.1 U14.E19(DDR_A20) U17.L3(ACT_n)
DDR_BA0: R253.1 U14.G18(DDR_A10) U17.N2(BA0)
DDR_BA1: R280.1 U14.N19(DDR_A29) U17.N8(BA1)
DDR_BG0: R255.1 U14.F18(DDR_A11) U17.M2(BG0)
DDR_BG1: R252.1 U14.L19(DDR_A27) U17.M9(BG1)
DDR_CASN: R278.1 U14.M19(DDR_A28) U17.M8(CAS_n/A15)
DDR_CKE: R259.1 U14.F17(DDR_A0) U17.K2(CKE)
DDR_CLK_N: R177.2 U14.L17(DDR_A5) U17.K8(CK_c)
DDR_CLK_P: R177.1 U14.M17(DDR_A4) U17.K7(CK_t)
DDR_CSN: R273.1 U14.J17(DDR_A2) U17.L7(CS_n)
DDR_DQ0: U14.W18(DDR_DQ0) U17.F7(LDQ1)
DDR_DQ1: U14.W17(DDR_DQ1) U17.H8(LDQ5)
DDR_DQ2: U14.V17(DDR_DQ2) U17.H7(LDQ3)
DDR_DQ3: U14.U17(DDR_DQ3) U17.J7(LDQ7)
DDR_DQ4: U14.T19(DDR_DQ4) U17.J3(LDQ6)
DDR_DQ5: U14.T18(DDR_DQ5) U17.H2(LDQ4)
DDR_DQ6: U14.U19(DDR_DQ6) U17.H3(LDQ2)
DDR_DQ7: U14.U18(DDR_DQ7) U17.G2(LDQ0)
DDR_DQ8: U14.C17(DDR_DQ8) U17.D7(UDQ7)
DDR_DQ9: U14.A18(DDR_DQ9) U17.B8(UDQ1)
DDR_DQ10: U14.B17(DDR_DQ10) U17.C7(UDQ3)
DDR_DQ11: U14.A17(DDR_DQ11) U17.C8(UDQ5)
DDR_DQ12: U14.D19(DDR_DQ12) U17.C3(UDQ2)
DDR_DQ13: U14.D18(DDR_DQ13) U17.D3(UDQ6)
DDR_DQ14: U14.D17(DDR_DQ14) U17.C2(UDQ4)
DDR_DQ15: U14.C18(DDR_DQ15) U17.A3(UDQ0)
DDR_DQM0: U14.T17(DDR_DQM0) U17.E7(LDM_n/LDBI_n)
DDR_DQM1: U14.C19(DDR_DQM1) U17.E2(UDM_n/UDBI_n)
DDR_DQS0_N: U14.V18(DDR_DQS0N) U17.F3(LDQS_c)
DDR_DQS0_P: U14.V19(DDR_DQS0P) U17.G3(LDQS_t)
DDR_DQS1_N: U14.B18(DDR_DQS1N) U17.A7(UDQS_c)
DDR_DQS1_P: U14.B19(DDR_DQS1P) U17.B7(UDQS_t)
DDR_ODT: R258.1 U14.J19(DDR_A3) U17.K3(ODT)
DDR_RASN: R276.1 U14.J18(DDR_A13) U17.L8(RAS_n/A16)
DDR_RESETN: R176.2 U14.E17(DDR_RESETN) U17.P1(RESET_n)
DDR_WEN: R257.1 U14.E18(DDR_A9) U17.L2(WE_n//A14)
DDR_ZQ: R112.2 U14.G16(DDR_ZQ)
NetC94_2: C94.2 R116.2 R118.2 U17.M1(VREFCA)
NetR113_2: R113.2 U17.E9(UZQ)
NetR179_2: R179.2 U17.F9(LZQ)

Not connected (* = marked no-connect by the designer): U14 G17(DDR_A1)* K17(DDR_VREF)* N17(DDR_A6)* P17(DDR_A7)*; U17 P9(ALERT_n)* T7(NF)*

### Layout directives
differential pair: DDR_CLK_N, DDR_CLK_P, DDR_DQS0_N, DDR_DQS0_P, DDR_DQS1_N, DDR_DQS1_P

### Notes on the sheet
- (near R116) 1%
- (near R118) 1%

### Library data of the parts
C70 C82 C94 C104-C106 C144 C146 C160 C178 C179 C181 C218 C226 C239 C252 C255-C259 C261 C265 C266 = MCD-00006: Capacitor, MLCC, 100nF, 16V, X7R, +/-10%, 0402, T=0.5mm; Part_Preference: Recommended; Manufacturer: YAGEO; Manufacturer_Part_Number: CC0402KRX7R7BB104; Alternate_Manufacturer: MURATA; Alternate_Manufacturer_Part_Number: GCM155R71C104KA55D; Order_Code_RS: 616-9701
C112 C172 = MCD-01341: Capacitor, MLCC, 10uF, 6V3, X5R, +/-20%, 0603, T=0,8mm; Part_Preference: Recommended; Manufacturer: MURATA; Manufacturer_Part_Number: GRM188R60J106ME47D; Alternate_Manufacturer_Part_Number: GRM188R60J106ME84D
C145 C254 = MCD-03140: as C39 on sheet PMIC
R112 R113 R179 = MCD-02253: Resistor,240R,0201,1%,1/20W; Part_Preference: Recommended; Manufacturer: YAGEO; Manufacturer_Part_Number: RC0201FR-07240RL
R116 R118 = MCD-00061: Resistor, 1K, 0402, +/-1%,1/16W; Part_Preference: Recommended; Manufacturer: YAGEO; Manufacturer_Part_Number: RC0402FR-071KL; Order_Code_RS: 9239235; Component_Country_Of_Origin: China; ShowFields: YES; ID: 2532
R176 = MCD-00053: Resistor,10K,0402,1%,1/16W; BMS_Part_Number: 9131590; Part_Preference: Recommended; Manufacturer: YAGEO; Manufacturer_Part_Number: RC0402FR-0710KL
R177 = MCD-01819: Resistor,100R,0402,0,5%,1/16W,±100ppm/°C; Part_Preference: Recommended; Manufacturer: YAGEO; Manufacturer_Part_Number: RC0402DR-07100RL
R252-R259 R263-R266 R268 R271 R273 R275-R284 = MCD-00054: Resistor, 56R, 0402, +/-1%, 1/16W; Part_Preference: Recommended; Manufacturer: YAGEO; Manufacturer_Part_Number: RC0402FR-0756RL
U14 = MCD-03768: as U14 on sheet STM32MP25XXAL I_Os
U17 = MCD-04020: Memory, DDR4 SDRAM, 1V2, 32Gbit, 1.6GHz, FBGA96; Part_Type: IC; Part_Preference: Recommended; Manufacturer: MICRON; ShowFields: YES; ID: 6136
